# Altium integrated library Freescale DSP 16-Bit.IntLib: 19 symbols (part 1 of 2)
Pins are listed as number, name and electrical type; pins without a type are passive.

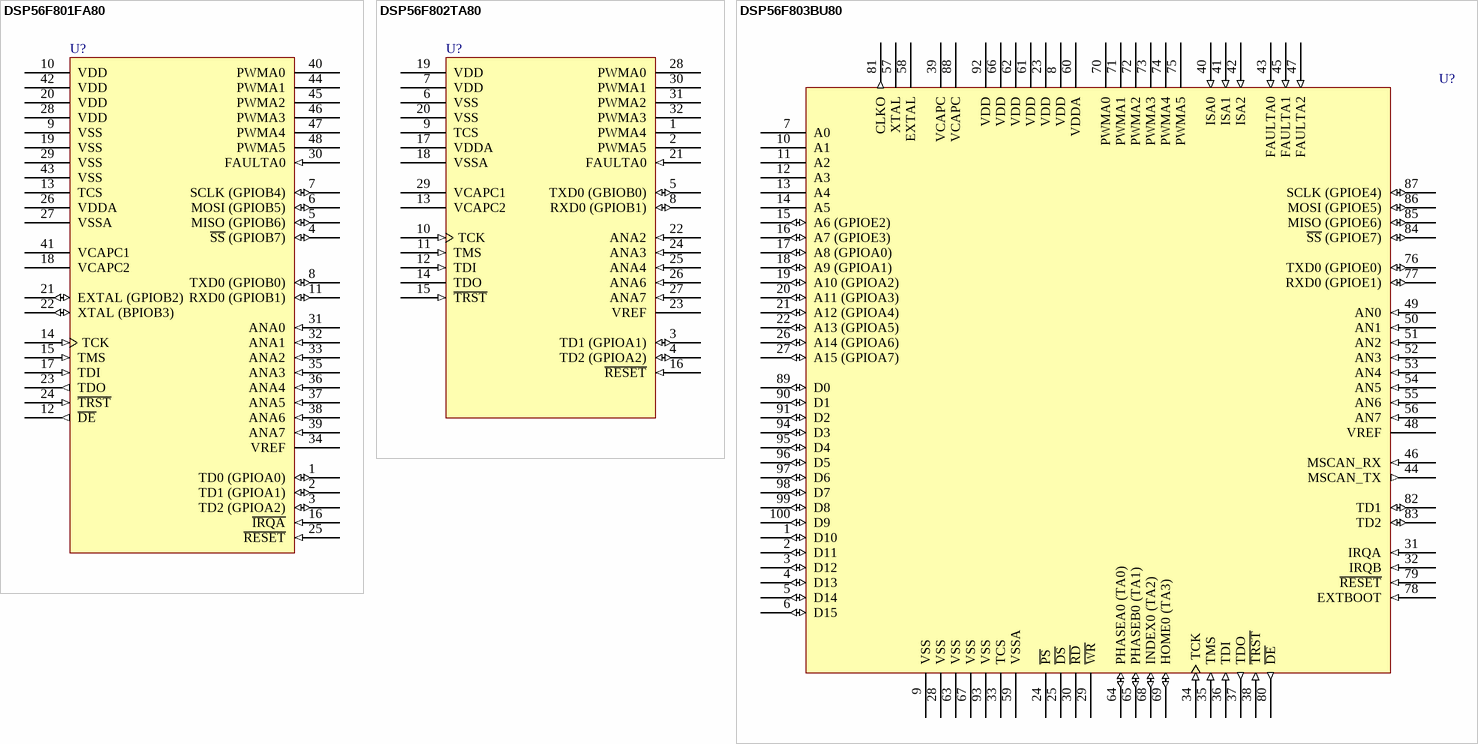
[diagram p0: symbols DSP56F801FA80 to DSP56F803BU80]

## DSP56F801FA80
designator U?
DSP56800 General Purpose 16-Bit Fixed Point DSP
footprint 932-03_N (Thin QFP, 48-Leads, Body 7x7mm, Pitch 0.5mm, IPC Medium Density)
footprint 932-03_L (Thin QFP, 48-Leads, Body 7x7mm, Pitch 0.5mm, IPC High Density)
footprint 932-03_M (Thin QFP, 48-Leads, Body 7x7mm, Pitch 0.5mm, IPC Low Density)
3D model DSP56F801-932-03 (48-Pin Thin Quad Flat Pack 0.5 mm Pitch)
pins: 1 TD0 (GPIOA0) (io), 2 TD1 (GPIOA1) (io), 3 TD2 (GPIOA2) (io), 4 ~{SS} (GPIOB7) (io), 5 MISO (GPIOB6) (io), 6 MOSI (GPIOB5) (io), 7 SCLK (GPIOB4) (io), 8 TXD0 (GPIOB0) (io), 9 VSS (power), 10 VDD (power), 11 RXD0 (GPIOB1) (io), 12 ~{DE} (out), 13 TCS, 14 TCK (in), 15 TMS (in), 16 ~{IRQA} (in), 17 TDI (in), 18 VCAPC2 (power), 19 VSS (power), 20 VDD (power), 21 EXTAL (GPIOB2) (io), 22 XTAL (BPIOB3) (io), 23 TDO (out), 24 ~{TRST} (in), 25 ~{RESET} (in), 26 VDDA (power), 27 VSSA (power), 28 VDD (power), 29 VSS (power), 30 FAULTA0 (in), 31 ANA0 (in), 32 ANA1 (in), 33 ANA2 (in), 34 VREF, 35 ANA3 (in), 36 ANA4 (in), 37 ANA5 (in), 38 ANA6 (in), 39 ANA7 (in), 40 PWMA0 (hiz), 41 VCAPC1 (power), 42 VDD (power), 43 VSS (power), 44 PWMA1 (hiz), 45 PWMA2 (hiz), 46 PWMA3 (hiz), 47 PWMA4 (hiz), 48 PWMA5 (hiz)

## DSP56F802TA80
designator U?
DSP56800 General Purpose 16-Bit Fixed Point DSP
footprint 873A_N (Thin QFP, 32-Leads, Body 7x7mm, Pitch 0.8mm, IPC Medium Density)
footprint 873A_L (Thin QFP, 32-Leads, Body 7x7mm, Pitch 0.8mm, IPC High Density)
footprint 873A_M (Thin QFP, 32-Leads, Body 7x7mm, Pitch 0.8mm, IPC Low Density)
3D model DSP56F802-873A (32-Pin Thin Quad Flat Pack 0.8 mm Pitch)
pins: 1 PWMA4 (hiz), 2 PWMA5 (hiz), 3 TD1 (GPIOA1) (io), 4 TD2 (GPIOA2) (io), 5 TXD0 (GBIOB0) (io), 6 VSS (power), 7 VDD (power), 8 RXD0 (GPIOB1) (io), 9 TCS, 10 TCK (in), 11 TMS (in), 12 TDI (in), 13 VCAPC2 (power), 14 TDO (hiz), 15 ~{TRST} (in), 16 ~{RESET} (in), 17 VDDA (power), 18 VSSA (power), 19 VDD (power), 20 VSS (power), 21 FAULTA0 (in), 22 ANA2 (in), 23 VREF, 24 ANA3 (in), 25 ANA4 (in), 26 ANA6 (in), 27 ANA7 (in), 28 PWMA0 (hiz), 29 VCAPC1 (power), 30 PWMA1 (hiz), 31 PWMA2 (hiz), 32 PWMA3 (hiz)

## DSP56F803BU80
designator U?
DSP56800 General Purpose 16-Bit Fixed Point DSP
footprint 842F-01_N (Thin QFP, 100-Leads, Body 14x14mm, Pitch 0.5mm, IPC Medium Density)
footprint 842F-01_L (Thin QFP, 100-Leads, Body 14x14mm, Pitch 0.5mm, IPC High Density)
footprint 842F-01_M (Thin QFP, 100-Leads, Body 14x14mm, Pitch 0.5mm, IPC Low Density)
3D model DSP56F803-842F-01 (100-Pin Thin Quad Flat Pack 0.5 mm Pitch)
pins: 1 D10 (io), 2 D11 (io), 3 D12 (io), 4 D13 (io), 5 D14 (io), 6 D15 (io), 7 A0 (hiz), 8 VDD (power), 9 VSS (power), 10 A1 (hiz), 11 A2 (hiz), 12 A3 (hiz), 13 A4 (hiz), 14 A5 (hiz), 15 A6 (GPIOE2) (io), 16 A7 (GPIOE3) (io), 17 A8 (GPIOA0) (io), 18 A9 (GPIOA1) (io), 19 A10 (GPIOA2) (io), 20 A11 (GPIOA3) (io), 21 A12 (GPIOA4) (io), 22 A13 (GPIOA5) (io), 23 VDD (power), 24 ~{PS} (hiz), 25 ~{DS} (hiz), 26 A14 (GPIOA6) (io), 27 A15 (GPIOA7) (io), 28 VSS (power), 29 ~{WR} (hiz), 30 ~{RD} (hiz), 31 IRQA (in), 32 IRQB (in), 33 TCS, 34 TCK (in), 35 TMS (in), 36 TDI (in), 37 TDO (out), 38 ~{TRST} (in), 39 VCAPC (power), 40 ISA0 (in), 41 ISA1 (in), 42 ISA2 (in), 43 FAULTA0 (in), 44 MSCAN_TX (out), 45 FAULTA1 (in), 46 MSCAN_RX (in), 47 FAULTA2 (in), 48 VREF, 49 AN0 (in), 50 AN1 (in), 51 AN2 (in), 52 AN3 (in), 53 AN4 (in), 54 AN5 (in), 55 AN6 (in), 56 AN7 (in), 57 XTAL, 58 EXTAL, 59 VSSA (power), 60 VDDA (power), 61 VDD (power), 62 VDD (power), 63 VSS (power), 64 PHASEA0 (TA0) (io), 65 PHASEB0 (TA1) (io), 66 VDD (power), 67 VSS (power), 68 INDEX0 (TA2) (io), 69 HOME0 (TA3) (io), 70 PWMA0 (hiz), 71 PWMA1 (hiz), 72 PWMA2 (hiz), 73 PWMA3 (hiz), 74 PWMA4 (hiz), 75 PWMA5 (hiz), 76 TXD0 (GPIOE0) (io), 77 RXD0 (GPIOE1) (io), 78 EXTBOOT (in), 79 ~{RESET} (in), 80 ~{DE} (out), 81 CLKO (out), 82 TD1 (io), 83 TD2 (io), 84 ~{SS} (GPIOE7) (io), 85 MISO (GPIOE6) (io), 86 MOSI (GPIOE5) (io), 87 SCLK (GPIOE4) (io), 88 VCAPC (power), 89 D0 (io), 90 D1 (io), 91 D2 (io), 92 VDD (power), 93 VSS (power), 94 D3 (io), 95 D4 (io), 96 D5 (io), 97 D6 (io), 98 D7 (io), 99 D8 (io), 100 D9 (io)

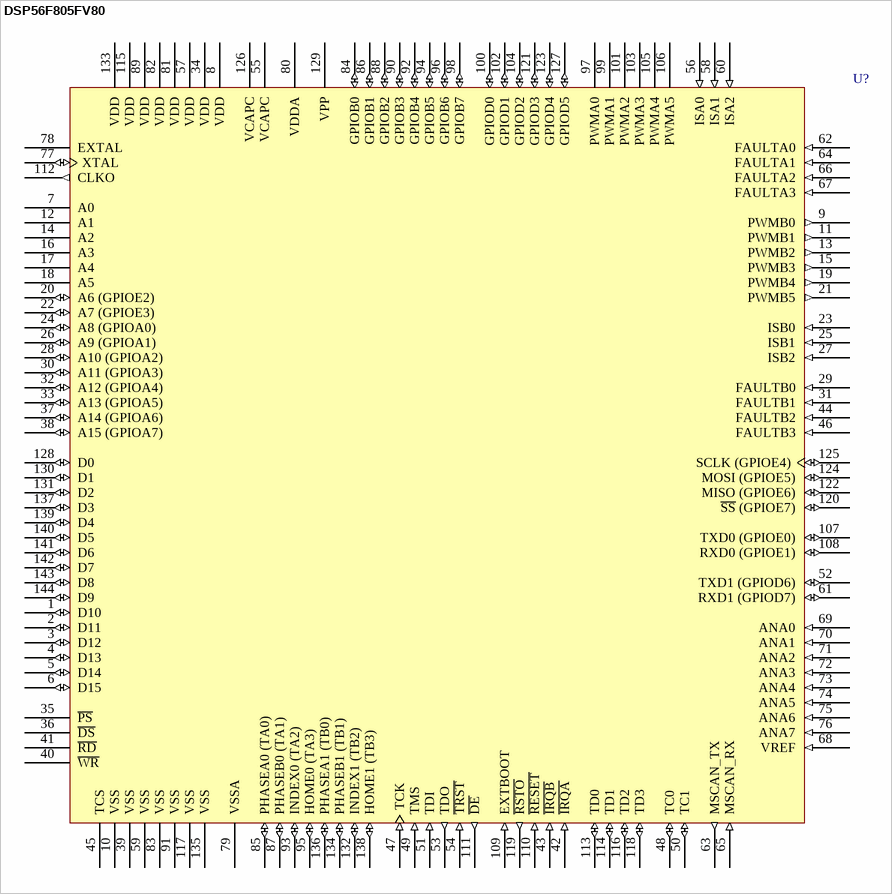
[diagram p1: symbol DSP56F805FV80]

## DSP56F805FV80
designator U?
DSP56800 General Purpose 16-Bit Fixed Point DSP
footprint 918-03_N (Thin QFP, 144-Leads, Body 20x20mm, Pitch 0.5mm, IPC Medium Density)
footprint 918-03_L (Thin QFP, 144-Leads, Body 20x20mm, Pitch 0.5mm, IPC High Density)
footprint 918-03_M (Thin QFP, 144-Leads, Body 20x20mm, Pitch 0.5mm, IPC Low Density)
3D model DSP56F805-918-03 (144-Pin Low Profile Quad Flat Pack 0.5 mm Pitch (918-03))
pins: 1 D10 (io), 2 D11 (io), 3 D12 (io), 4 D13 (io), 5 D14 (io), 6 D15 (io), 7 A0 (hiz), 8 VDD (power), 9 PWMB0 (out), 10 VSS (power), 11 PWMB1 (out), 12 A1 (hiz), 13 PWMB2 (out), 14 A2 (hiz), 15 PWMB3 (out), 16 A3 (hiz), 17 A4 (hiz), 18 A5 (hiz), 19 PWMB4 (out), 20 A6 (GPIOE2) (io), 21 PWMB5 (out), 22 A7 (GPIOE3) (io), 23 ISB0 (in), 24 A8 (GPIOA0) (io), 25 ISB1 (in), 26 A9 (GPIOA1) (io), 27 ISB2 (in), 28 A10 (GPIOA2) (io), 29 FAULTB0 (in), 30 A11 (GPIOA3) (io), 31 FAULTB1 (in), 32 A12 (GPIOA4) (io), 33 A13 (GPIOA5) (io), 34 VDD (power), 35 ~{PS} (hiz), 36 ~{DS} (hiz), 37 A14 (GPIOA6) (io), 38 A15 (GPIOA7) (io), 39 VSS (power), 40 ~{WR} (hiz), 41 ~{RD} (hiz), 42 ~{IRQA} (in), 43 ~{IRQB} (in), 44 FAULTB2 (in), 45 TCS, 46 FAULTB3 (in), 47 TCK (in), 48 TC0 (io), 49 TMS (in), 50 TC1 (io), 51 TDI (in), 52 TXD1 (GPIOD6) (io), 53 TDO (out), 54 ~{TRST} (in), 55 VCAPC (power), 56 ISA0 (in), 57 VDD (power), 58 ISA1 (in), 59 VSS (power), 60 ISA2 (in), 61 RXD1 (GPIOD7) (io), 62 FAULTA0 (in), 63 MSCAN_TX (out), 64 FAULTA1 (in), 65 MSCAN_RX (in), 66 FAULTA2 (in), 67 FAULTA3 (in), 68 VREF (in), 69 ANA0 (in), 70 ANA1 (in), 71 ANA2 (in), 72 ANA3 (in), 73 ANA4 (in), 74 ANA5 (in), 75 ANA6 (in), 76 ANA7 (in), 77 XTAL (io), 78 EXTAL, 79 VSSA (power), 80 VDDA (power), 81 VDD (power), 82 VDD (power), 83 VSS (power), 84 GPIOB0 (io), 85 PHASEA0 (TA0) (io), 86 GPIOB1 (io), 87 PHASEB0 (TA1) (io), 88 GPIOB2 (io), 89 VDD (power), 90 GPIOB3 (io), 91 VSS (power), 92 GPIOB4 (io), 93 INDEX0 (TA2) (io), 94 GPIOB5 (io), 95 HOME0 (TA3) (io), 96 GPIOB6 (io), 97 PWMA0 (hiz), 98 GPIOB7 (io), 99 PWMA1 (hiz), 100 GPIOD0 (io), 101 PWMA2 (hiz), 102 GPIOD1 (io), 103 PWMA3 (hiz), 104 GPIOD2 (io), 105 PWMA4 (hiz), 106 PWMA5 (hiz), 107 TXD0 (GPIOE0) (io), 108 RXD0 (GPIOE1) (io), 109 EXTBOOT (in), 110 ~{RESET} (in), 111 ~{DE} (out), 112 CLKO (out), 113 TD0 (io), 114 TD1 (io), 115 VDD (power), 116 TD2 (io), 117 VSS (power), 118 TD3 (io), 119 ~{RSTO} (out), 120 ~{SS} (GPIOE7) (io), 121 GPIOD3 (io), 122 MISO (GPIOE6) (io), 123 GPIOD4 (io), 124 MOSI (GPIOE5) (io), 125 SCLK (GPIOE4) (io), 126 VCAPC (power), 127 GPIOD5 (io), 128 D0 (io), 129 VPP (power), 130 D1 (io), 131 D2 (io), 132 INDEX1 (TB2) (io), 133 VDD (power), 134 PHASEB1 (TB1) (io), 135 VSS (power), 136 PHASEA1 (TB0) (io), 137 D3 (io), 138 HOME1 (TB3) (io), 139 D4 (io), 140 D5 (io), 141 D6 (io), 142 D7 (io), 143 D8 (io), 144 D9 (io)

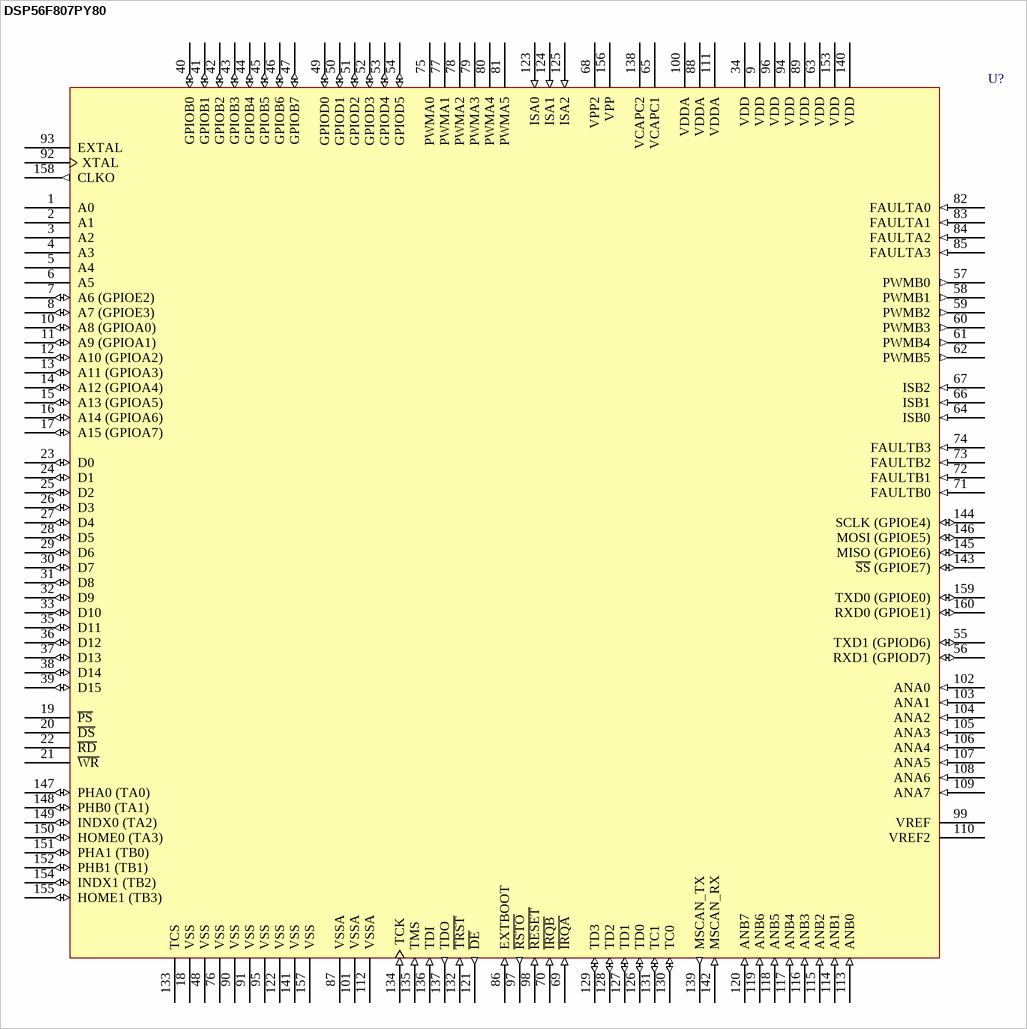
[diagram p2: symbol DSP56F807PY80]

## DSP56F807PY80
designator U?
DSP56800 General Purpose 16-Bit Fixed Point DSP
footprint 1259-01_N (Thin QFP, 160-Leads, Body 24x24mm, Pitch 0.5mm, IPC Medium Density)
footprint 1259-01_L (Thin QFP, 160-Leads, Body 24x24mm, Pitch 0.5mm, IPC High Density)
footprint 1259-01_M (Thin QFP, 160-Leads, Body 24x24mm, Pitch 0.5mm, IPC Low Density)
3D model DSP56F807-1259-01 (160-Pin Thin Quad Flat Pack 0.5 mm Pitch)
pins: 1 A0 (hiz), 2 A1 (hiz), 3 A2 (hiz), 4 A3 (hiz), 5 A4 (hiz), 6 A5 (hiz), 7 A6 (GPIOE2) (io), 8 A7 (GPIOE3) (io), 9 VDD (power), 10 A8 (GPIOA0) (io), 11 A9 (GPIOA1) (io), 12 A10 (GPIOA2) (io), 13 A11 (GPIOA3) (io), 14 A12 (GPIOA4) (io), 15 A13 (GPIOA5) (io), 16 A14 (GPIOA6) (io), 17 A15 (GPIOA7) (io), 18 VSS (power), 19 ~{PS} (hiz), 20 ~{DS} (hiz), 21 ~{WR} (hiz), 22 ~{RD} (hiz), 23 D0 (io), 24 D1 (io), 25 D2 (io), 26 D3 (io), 27 D4 (io), 28 D5 (io), 29 D6 (io), 30 D7 (io), 31 D8 (io), 32 D9 (io), 33 D10 (io), 34 VDD (power), 35 D11 (io), 36 D12 (io), 37 D13 (io), 38 D14 (io), 39 D15 (io), 40 GPIOB0 (io), 41 GPIOB1 (io), 42 GPIOB2 (io), 43 GPIOB3 (io), 44 GPIOB4 (io), 45 GPIOB5 (io), 46 GPIOB6 (io), 47 GPIOB7 (io), 48 VSS (power), 49 GPIOD0 (io), 50 GPIOD1 (io), 51 GPIOD2 (io), 52 GPIOD3 (io), 53 GPIOD4 (io), 54 GPIOD5 (io), 55 TXD1 (GPIOD6) (io), 56 RXD1 (GPIOD7) (io), 57 PWMB0 (out), 58 PWMB1 (out), 59 PWMB2 (out), 60 PWMB3 (out), 61 PWMB4 (out), 62 PWMB5 (out), 63 VDD (power), 64 ISB0 (in), 65 VCAPC1 (power), 66 ISB1 (in), 67 ISB2 (in), 68 VPP2, 69 ~{IRQA} (in), 70 ~{IRQB} (in), 71 FAULTB0 (in), 72 FAULTB1 (in), 73 FAULTB2 (in), 74 FAULTB3 (in), 75 PWMA0 (hiz), 76 VSS (power), 77 PWMA1 (hiz), 78 PWMA2 (hiz), 79 PWMA3 (hiz), 80 PWMA4 (hiz), 81 PWMA5 (hiz), 82 FAULTA0 (in), 83 FAULTA1 (in), 84 FAULTA2 (in), 85 FAULTA3 (in), 86 EXTBOOT (in), 87 VSSA (power), 88 VDDA (power), 89 VDD (power), 90 VSS (power), 91 VSS (power), 92 XTAL, 93 EXTAL, 94 VDD (power), 95 VSS (power), 96 VDD (power), 97 ~{RSTO} (out), 98 ~{RESET} (in), 99 VREF, 100 VDDA (power), 101 VSSA (power), 102 ANA0 (in), 103 ANA1 (in), 104 ANA2 (in), 105 ANA3 (in), 106 ANA4 (in), 107 ANA5 (in), 108 ANA6 (in), 109 ANA7 (in), 110 VREF2, 111 VDDA (power), 112 VSSA (power), 113 ANB0 (in), 114 ANB1 (in), 115 ANB2 (in), 116 ANB3 (in), 117 ANB4 (in), 118 ANB5 (in), 119 ANB6 (in), 120 ANB7 (in), 121 ~{DE} (out), 122 VSS (power), 123 ISA0 (in), 124 ISA1 (in), 125 ISA2 (in), 126 TD0 (io), 127 TD1 (io), 128 TD2 (io), 129 TD3 (io), 130 TC0 (io), 131 TC1 (io), 132 ~{TRST} (in), 133 TCS, 134 TCK (in), 135 TMS (in), 136 TDI (in), 137 TDO (out), 138 VCAPC2 (power), 139 MSCAN_TX (out), 140 VDD (power), 141 VSS (power), 142 MSCAN_RX (in), 143 ~{SS} (GPIOE7) (io), 144 SCLK (GPIOE4) (io), 145 MISO (GPIOE6) (io), 146 MOSI (GPIOE5) (io), 147 PHA0 (TA0) (io), 148 PHB0 (TA1) (io), 149 INDX0 (TA2) (io), 150 HOME0 (TA3) (io), 151 PHA1 (TB0) (io), 152 PHB1 (TB1) (io), 153 VDD (power), 154 INDX1 (TB2) (io), 155 HOME1 (TB3) (io), 156 VPP, 157 VSS (power), 158 CLKO (out), 159 TXD0 (GPIOE0) (io), 160 RXD0 (GPIOE1) (io)

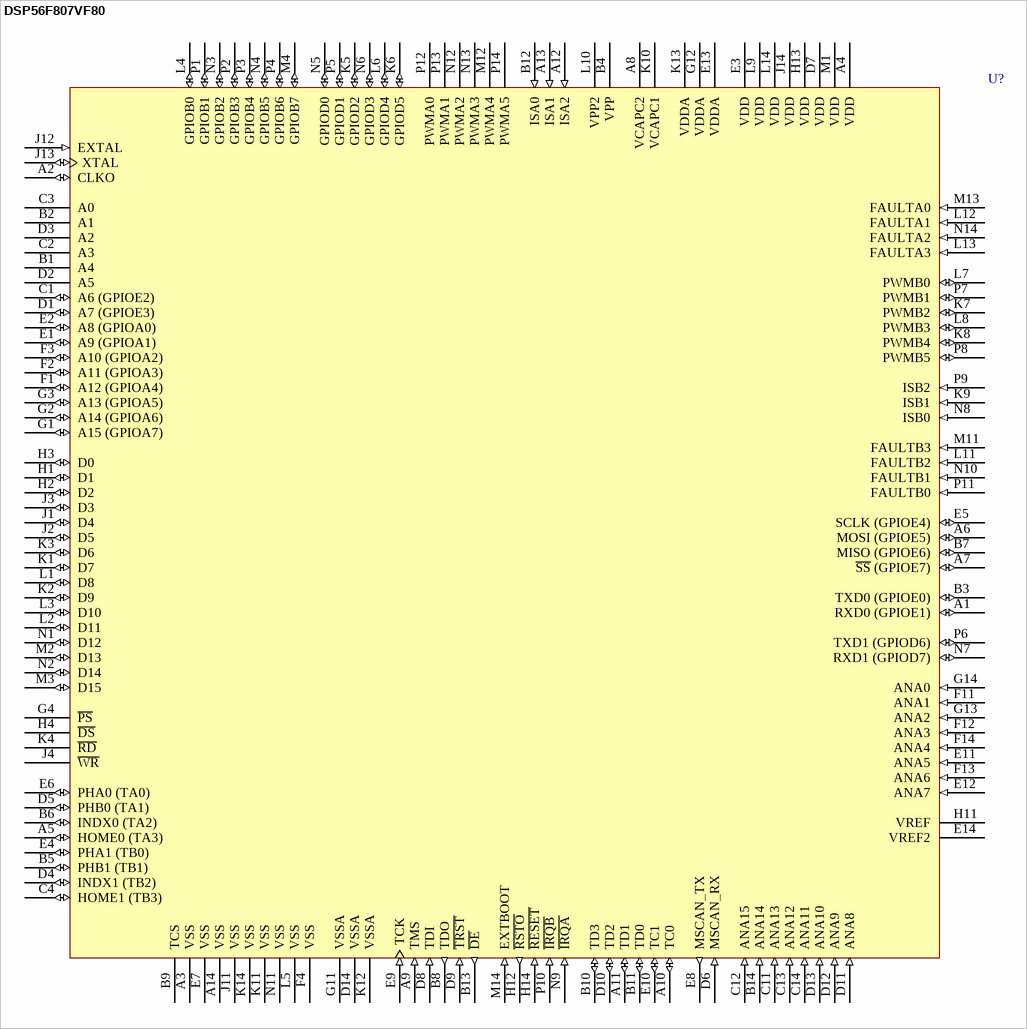
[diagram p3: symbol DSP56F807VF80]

## DSP56F807VF80
designator U?
DSP56800 General Purpose 16-Bit Fixed Point DSP
footprint 1268-01 (BGA, 160-Leads, Body 15x15mm, Pitch 1mm)
3D model DSP56F807-1268-01 (160-Ball MAP-Ball Grid Array 1 mm Pitch)
pins: A1 RXD0 (GPIOE1) (io), A2 CLKO (io), A3 VSS (power), A4 VDD (power), A5 HOME0 (TA3) (io), A6 MOSI (GPIOE5) (io), A7 ~{SS} (GPIOE7) (io), A8 VCAPC2, A9 TMS (in), A10 TC0 (io), A11 TD1 (io), A12 ISA2 (in), A13 ISA1 (in), A14 VSS (power), B1 A4 (hiz), B2 A1 (hiz), B3 TXD0 (GPIOE0) (io), B4 VPP, B5 PHB1 (TB1) (io), B6 INDX0 (TA2) (io), B7 MISO (GPIOE6) (io), B8 TDO (out), B9 TCS, B10 TD3 (io), B11 TD0 (io), B12 ISA0 (in), B13 ~{DE} (out), B14 ANA14 (in), C1 A6 (GPIOE2) (io), C2 A3 (hiz), C3 A0 (hiz), C4 HOME1 (TB3) (io), C11 ANA13 (in), C12 ANA15 (in), C13 ANA12 (in), C14 ANA11 (in), D1 A7 (GPIOE3) (io), D2 A5 (hiz), D3 A2 (hiz), D4 INDX1 (TB2) (io), D5 PHB0 (TA1) (io), D6 MSCAN_RX (in), D7 VDD (power), D8 TDI (in), D9 ~{TRST} (in), D10 TD2 (io), D11 ANA8 (in), D12 ANA9 (in), D13 ANA10 (in), D14 VSSA (power), E1 A9 (GPIOA1) (io), E2 A8 (GPIOA0) (io), E3 VDD (power), E4 PHA1 (TB0) (io), E5 SCLK (GPIOE4) (io), E6 PHA0 (TA0) (io), E7 VSS (power), E8 MSCAN_TX (out), E9 TCK (in), E10 TC1 (io), E11 ANA5 (in), E12 ANA7 (in), E13 VDDA (power), E14 VREF2, F1 A12 (GPIOA4) (io), F2 A11 (GPIOA3) (io), F3 A10 (GPIOA2) (io), F4 VSS (power), F11 ANA1 (in), F12 ANA3 (in), F13 ANA6 (in), F14 ANA4 (in), G1 A15 (GPIOA7) (io), G2 A14 (GPIOA6) (io), G3 A13 (GPIOA5) (io), G4 ~{PS} (hiz), G11 VSSA (power), G12 VDDA (power), G13 ANA2 (in), G14 ANA0 (in), H1 D1 (io), H2 D2 (io), H3 D0 (io), H4 ~{DS} (hiz), H11 VREF, H12 ~{RSTO} (out), H13 VDD (power), H14 ~{RESET} (in), J1 D4 (io), J2 D5 (io), J3 D3 (io), J4 ~{WR} (hiz), J11 VSS (power), J12 EXTAL (in), J13 XTAL (io), J14 VDD (power), K1 D7 (io), K2 D9 (io), K3 D6 (io), K4 ~{RD} (hiz), K5 GPIOD2 (io), K6 GPIOD5 (io), K7 PWMB2 (io), K8 PWMB4 (io), K9 ISB1 (in), K10 VCAPC1, K11 VSS (power), K12 VSSA (power), K13 VDDA (power), K14 VSS (power), L1 D8 (io), L2 D11 (io), L3 D10 (io), L4 GPIOB0 (io), L5 VSS (power), L6 GPIOD4 (io), L7 PWMB0 (io), L8 PWMB3 (io), L9 VDD (power), L10 VPP2, L11 FAULTB2 (in), L12 FAULTA1 (in), L13 FAULTA3 (in), L14 VDD (power), M1 VDD (power), M2 D13 (io), M3 D15 (io), M4 GPIOB7 (io), M11 FAULTB3 (in), M12 PWMA4 (hiz), M13 FAULTA0 (in), M14 EXTBOOT (in), N1 D12 (io), N2 D14 (io), N3 GPIOB2 (io), N4 GPIOB5 (io), N5 GPIOD0 (io), N6 GPIOD3 (io), N7 RXD1 (GPIOD7) (io), N8 ISB0 (in), N9 ~{IRQA} (in), N10 FAULTB1 (in), N11 VSS (power), N12 PWMA2 (hiz), N13 PWMA3 (hiz), N14 FAULTA2 (in), P1 GPIOB1 (io), P2 GPIOB3 (io), P3 GPIOB4 (io), P4 GPIOB6 (io), P5 GPIOD1 (io), P6 TXD1 (GPIOD6) (io), P7 PWMB1 (io), P8 PWMB5 (io), P9 ISB2 (in), P10 ~{IRQB} (in), P11 FAULTB0 (in), P12 PWMA0 (hiz), P13 PWMA1 (hiz), P14 PWMA5 (hiz)

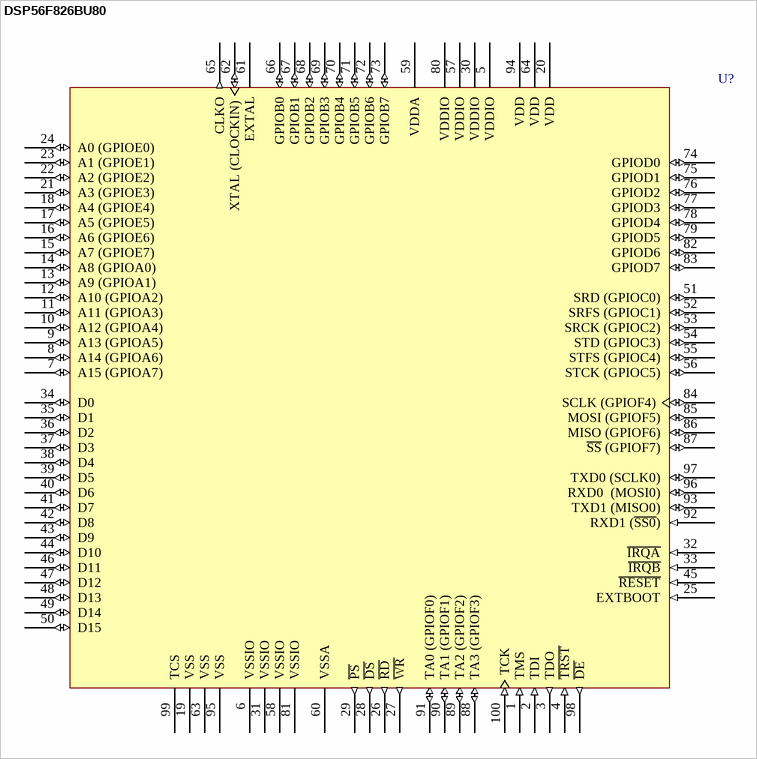
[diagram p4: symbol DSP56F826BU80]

## DSP56F826BU80
designator U?
DSP56800 General Purpose 16-Bit Fixed Point DSP
footprint 842F-01_N (Thin QFP, 100-Leads, Body 14x14mm, Pitch 0.5mm, IPC Medium Density)
footprint 842F-01_L (Thin QFP, 100-Leads, Body 14x14mm, Pitch 0.5mm, IPC High Density)
footprint 842F-01_M (Thin QFP, 100-Leads, Body 14x14mm, Pitch 0.5mm, IPC Low Density)
3D model DSP56F826-842F-01 (100-Pin Thin Quad Flat Pack 0.5 mm Pitch)
pins: 1 TMS (in), 2 TDI (in), 3 TDO (out), 4 ~{TRST} (in), 5 VDDIO (power), 6 VSSIO (power), 7 A15 (GPIOA7) (io), 8 A14 (GPIOA6) (io), 9 A13 (GPIOA5) (io), 10 A12 (GPIOA4) (io), 11 A11 (GPIOA3) (io), 12 A10 (GPIOA2) (io), 13 A9 (GPIOA1) (io), 14 A8 (GPIOA0) (io), 15 A7 (GPIOE7) (io), 16 A6 (GPIOE6) (io), 17 A5 (GPIOE5) (io), 18 A4 (GPIOE4) (io), 19 VSS (power), 20 VDD (power), 21 A3 (GPIOE3) (io), 22 A2 (GPIOE2) (io), 23 A1 (GPIOE1) (io), 24 A0 (GPIOE0) (io), 25 EXTBOOT (in), 26 ~{RD} (out), 27 ~{WR} (out), 28 ~{DS} (out), 29 ~{PS} (out), 30 VDDIO (power), 31 VSSIO (power), 32 ~{IRQA} (in), 33 ~{IRQB} (in), 34 D0 (io), 35 D1 (io), 36 D2 (io), 37 D3 (io), 38 D4 (io), 39 D5 (io), 40 D6 (io), 41 D7 (io), 42 D8 (io), 43 D9 (io), 44 D10 (io), 45 ~{RESET} (in), 46 D11 (io), 47 D12 (io), 48 D13 (io), 49 D14 (io), 50 D15 (io), 51 SRD (GPIOC0) (io), 52 SRFS (GPIOC1) (io), 53 SRCK (GPIOC2) (io), 54 STD (GPIOC3) (io), 55 STFS (GPIOC4) (io), 56 STCK (GPIOC5) (io), 57 VDDIO (power), 58 VSSIO (power), 59 VDDA (power), 60 VSSA (power), 61 EXTAL, 62 XTAL (CLOCKIN) (io), 63 VSS (power), 64 VDD (power), 65 CLKO (out), 66 GPIOB0 (io), 67 GPIOB1 (io), 68 GPIOB2 (io), 69 GPIOB3 (io), 70 GPIOB4 (io), 71 GPIOB5 (io), 72 GPIOB6 (io), 73 GPIOB7 (io), 74 GPIOD0 (io), 75 GPIOD1 (io), 76 GPIOD2 (io), 77 GPIOD3 (io), 78 GPIOD4 (io), 79 GPIOD5 (io), 80 VDDIO (power), 81 VSSIO (power), 82 GPIOD6 (io), 83 GPIOD7 (io), 84 SCLK (GPIOF4) (io), 85 MOSI (GPIOF5) (io), 86 MISO (GPIOF6) (io), 87 ~{SS} (GPIOF7) (io), 88 TA3 (GPIOF3) (io), 89 TA2 (GPIOF2) (io), 90 TA1 (GPIOF1) (io), 91 TA0 (GPIOF0) (io), 92 RXD1 (~{SS0}) (in), 93 TXD1 (MISO0) (io), 94 VDD (power), 95 VSS (power), 96 RXD0  (MOSI0) (io), 97 TXD0 (SCLK0) (io), 98 ~{DE} (out), 99 TCS, 100 TCK (in)

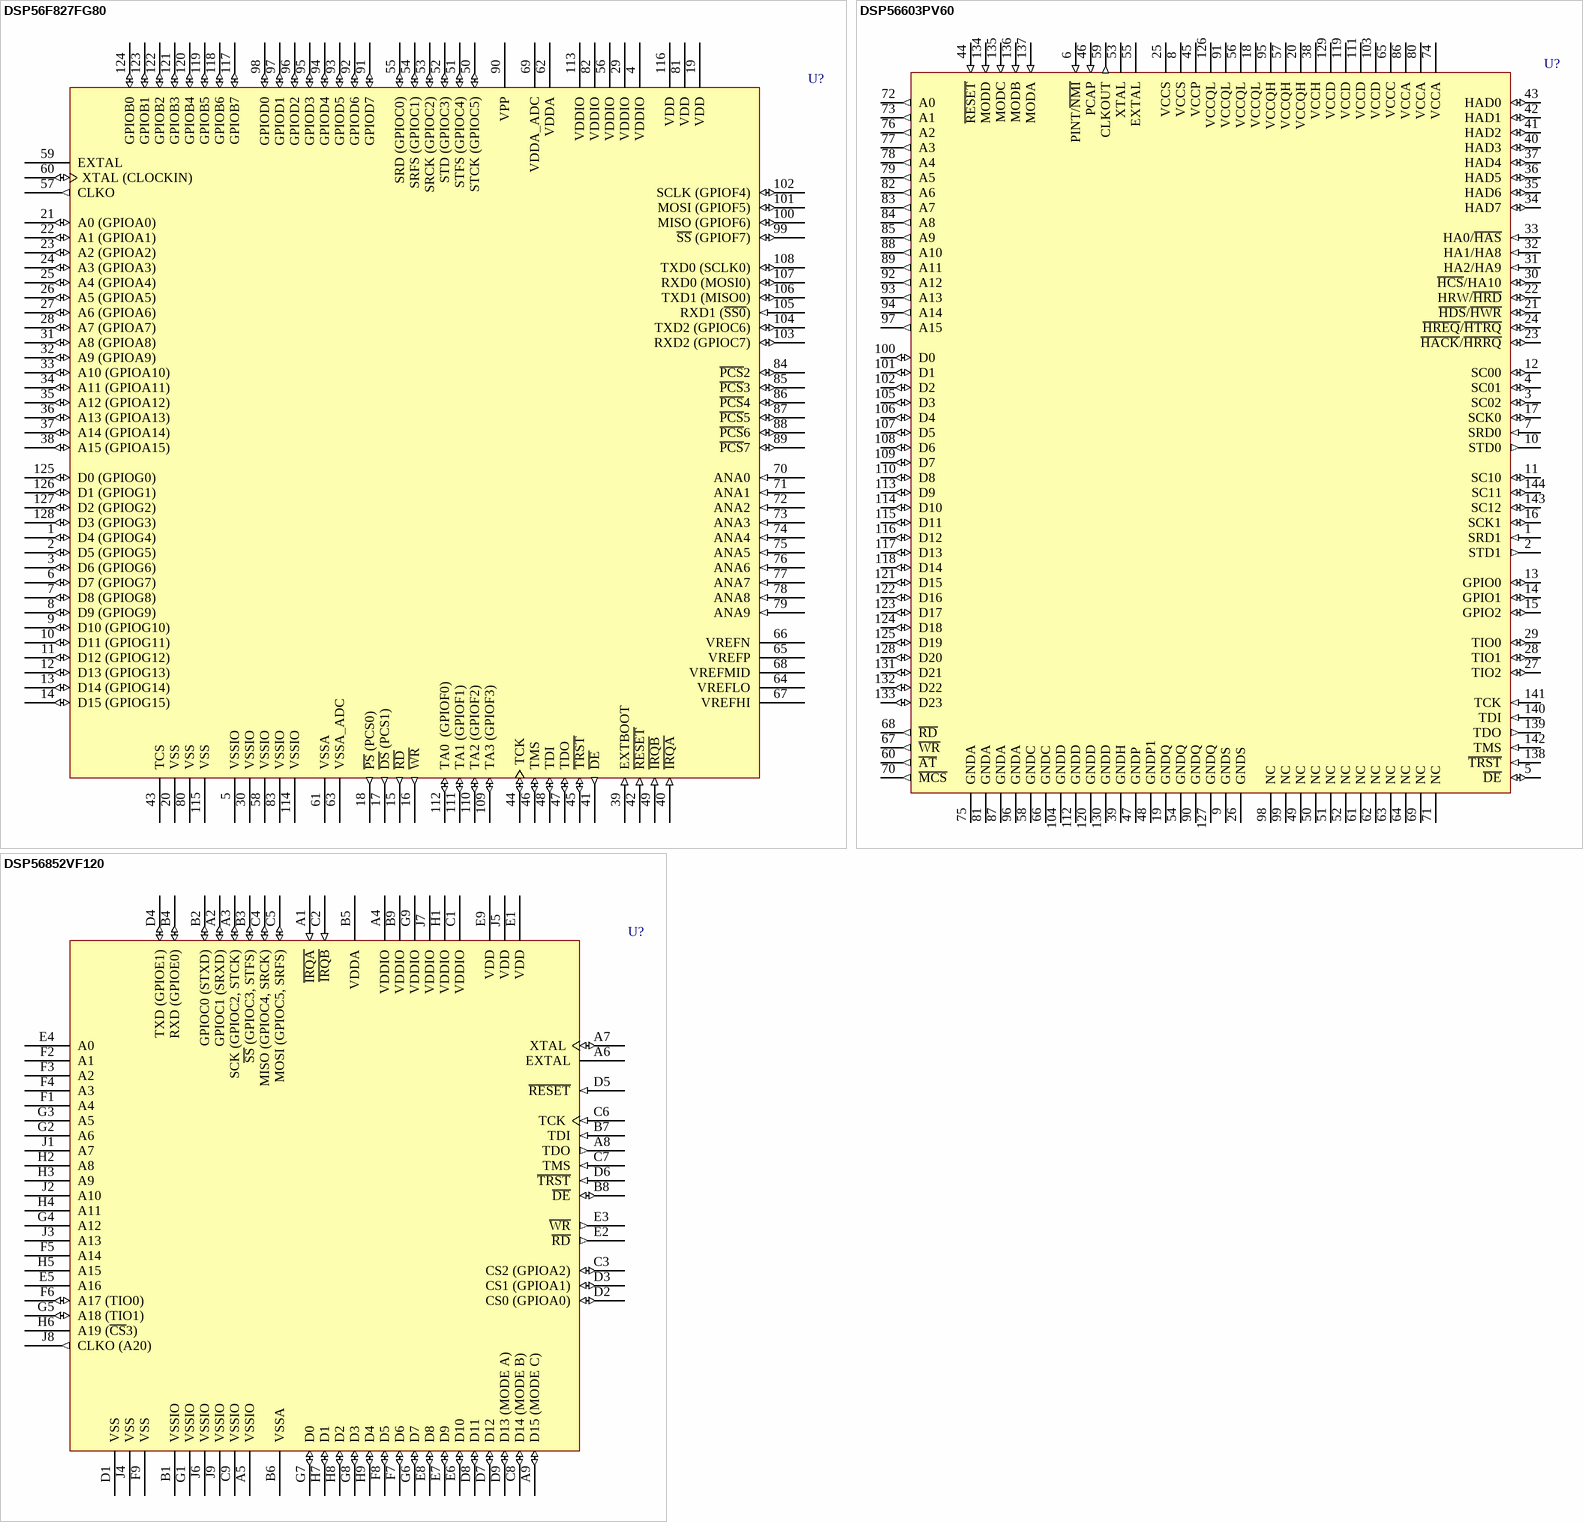
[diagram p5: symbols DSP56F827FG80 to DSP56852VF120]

## DSP56F827FG80
designator U?
DSP56800 General Purpose 16-Bit Fixed Point DSP
footprint 1129-01_N (Thin QFP, 128-Leads, Body 20x14 mm, Pitch 0.5mm, IPC Medium Density)
footprint 1129-01_L (Thin QFP, 128-Leads, Body 20x14 mm, Pitch 0.5mm, IPC High Density)
footprint 1129-01_M (Thin QFP, 128-Leads, Body 20x14 mm, Pitch 0.5mm, IPC Low Density)
3D model DSP56F827-1129-01 (128-Pin Thin Quad Flat Pack Rectangular 0.5 mm Pitch)
pins: 1 D4 (GPIOG4) (io), 2 D5 (GPIOG5) (io), 3 D6 (GPIOG6) (io), 4 VDDIO (power), 5 VSSIO (power), 6 D7 (GPIOG7) (io), 7 D8 (GPIOG8) (io), 8 D9 (GPIOG9) (io), 9 D10 (GPIOG10) (io), 10 D11 (GPIOG11) (io), 11 D12 (GPIOG12) (io), 12 D13 (GPIOG13) (io), 13 D14 (GPIOG14) (io), 14 D15 (GPIOG15) (io), 15 ~{RD} (out), 16 ~{WR} (out), 17 ~{DS} (PCS1) (out), 18 ~{PS} (PCS0) (out), 19 VDD (power), 20 VSS (power), 21 A0 (GPIOA0) (io), 22 A1 (GPIOA1) (io), 23 A2 (GPIOA2) (io), 24 A3 (GPIOA3) (io), 25 A4 (GPIOA4) (io), 26 A5 (GPIOA5) (io), 27 A6 (GPIOA6) (io), 28 A7 (GPIOA7) (io), 29 VDDIO (power), 30 VSSIO (power), 31 A8 (GPIOA8) (io), 32 A9 (GPIOA9) (io), 33 A10 (GPIOA10) (io), 34 A11 (GPIOA11) (io), 35 A12 (GPIOA12) (io), 36 A13 (GPIOA13) (io), 37 A14 (GPIOA14) (io), 38 A15 (GPIOA15) (io), 39 EXTBOOT (in), 40 ~{IRQA} (in), 41 ~{DE} (out), 42 ~{RESET} (in), 43 TCS, 44 TCK (io), 45 ~{TRST} (io), 46 TMS (io), 47 TDO (io), 48 TDI (io), 49 ~{IRQB} (in), 50 STCK (GPIOC5) (io), 51 STFS (GPIOC4) (io), 52 STD (GPIOC3) (io), 53 SRCK (GPIOC2) (io), 54 SRFS (GPIOC1) (io), 55 SRD (GPIOC0) (io), 56 VDDIO (power), 57 CLKO (out), 58 VSSIO (power), 59 EXTAL, 60 XTAL (CLOCKIN) (io), 61 VSSA (power), 62 VDDA (power), 63 VSSA_ADC (power), 64 VREFLO, 65 VREFP, 66 VREFN, 67 VREFHI, 68 VREFMID, 69 VDDA_ADC (power), 70 ANA0 (in), 71 ANA1 (in), 72 ANA2 (in), 73 ANA3 (in), 74 ANA4 (in), 75 ANA5 (in), 76 ANA6 (in), 77 ANA7 (in), 78 ANA8 (in), 79 ANA9 (in), 80 VSS (power), 81 VDD (power), 82 VDDIO (power), 83 VSSIO (power), 84 ~{PCS}2 (io), 85 ~{PCS}3 (io), 86 ~{PCS}4 (io), 87 ~{PCS}5 (io), 88 ~{PCS}6 (io), 89 ~{PCS}7 (io), 90 VPP, 91 GPIOD7 (io), 92 GPIOD6 (io), 93 GPIOD5 (io), 94 GPIOD4 (io), 95 GPIOD3 (io), 96 GPIOD2 (io), 97 GPIOD1 (io), 98 GPIOD0 (io), 99 ~{SS} (GPIOF7) (io), 100 MISO (GPIOF6) (io), 101 MOSI (GPIOF5) (io), 102 SCLK (GPIOF4) (io), 103 RXD2 (GPIOC7) (io), 104 TXD2 (GPIOC6) (io), 105 RXD1 (~{SS0}) (in), 106 TXD1 (MISO0) (io), 107 RXD0 (MOSI0) (io), 108 TXD0 (SCLK0) (io), 109 TA3 (GPIOF3) (io), 110 TA2 (GPIOF2) (io), 111 TA1 (GPIOF1) (io), 112 TA0  (GPIOF0) (io), 113 VDDIO (power), 114 VSSIO (power), 115 VSS (power), 116 VDD (power), 117 GPIOB7 (io), 118 GPIOB6 (io), 119 GPIOB5 (io), 120 GPIOB4 (io), 121 GPIOB3 (io), 122 GPIOB2 (io), 123 GPIOB1 (io), 124 GPIOB0 (io), 125 D0 (GPIOG0) (io), 126 D1 (GPIOG1) (io), 127 D2 (GPIOG2) (io), 128 D3 (GPIOG3) (io)

## DSP56603PV60
designator U?
16-Bit Digital Signal Processor
footprint 918-03_N (Thin QFP, 144-Leads, Body 20x20mm, Pitch 0.5mm, IPC Medium Density)
footprint 918-03_L (Thin QFP, 144-Leads, Body 20x20mm, Pitch 0.5mm, IPC High Density)
footprint 918-03_M (Thin QFP, 144-Leads, Body 20x20mm, Pitch 0.5mm, IPC Low Density)
3D model DSP56603-918-03 (144-Pin Low Profile Quad Flat Pack 0.5 mm Pitch (918-03))
pins: 1 SRD1 (in), 2 STD1 (out), 3 SC02 (io), 4 SC01 (io), 5 ~{DE} (io), 6 PINT/~{NMI} (in), 7 SRD0 (in), 8 VCCS (power), 9 GNDS (power), 10 STD0 (out), 11 SC10 (io), 12 SC00 (io), 13 GPIO0 (io), 14 GPIO1 (io), 15 GPIO2 (io), 16 SCK1 (io), 17 SCK0 (io), 18 VCCQL (power), 19 GNDQ (power), 20 VCCQH (power), 21 ~{HDS}/~{HWR} (io), 22 HRW/~{HRD} (io), 23 ~{HACK}/~{HRRQ} (io), 24 ~{HREQ}/~{HTRQ} (io), 25 VCCS (power), 26 GNDS (power), 27 TIO2 (io), 28 TIO1 (io), 29 TIO0 (io), 30 ~{HCS}/HA10 (io), 31 HA2/HA9 (in), 32 HA1/HA8 (in), 33 HA0/~{HAS} (in), 34 HAD7 (io), 35 HAD6 (io), 36 HAD5 (io), 37 HAD4 (io), 38 VCCH (power), 39 GNDH (power), 40 HAD3 (io), 41 HAD2 (io), 42 HAD1 (io), 43 HAD0 (io), 44 ~{RESET} (in), 45 VCCP (power), 46 PCAP (in), 47 GNDP (power), 48 GNDP1 (power), 49 NC, 50 NC, 51 NC, 52 NC, 53 XTAL, 54 GNDQ (power), 55 EXTAL, 56 VCCQL (power), 57 VCCQH (power), 58 GNDC (power), 59 CLKOUT (out), 60 ~{AT} (out), 61 NC, 62 NC, 63 NC, 64 NC, 65 VCCC (power), 66 GNDC (power), 67 ~{WR} (out), 68 ~{RD} (out), 69 NC, 70 ~{MCS} (out), 71 NC, 72 A0 (out), 73 A1 (out), 74 VCCA (power), 75 GNDA (power), 76 A2 (out), 77 A3 (out), 78 A4 (out), 79 A5 (out), 80 VCCA (power), 81 GNDA (power), 82 A6 (out), 83 A7 (out), 84 A8 (out), 85 A9 (out), 86 VCCA (power), 87 GNDA (power), 88 A10 (out), 89 A11 (out), 90 GNDQ (power), 91 VCCQL (power), 92 A12 (out), 93 A13 (out), 94 A14 (out), 95 VCCQH (power), 96 GNDA (power), 97 A15 (out), 98 NC, 99 NC, 100 D0 (io), 101 D1 (io), 102 D2 (io), 103 VCCD (power), 104 GNDD (power), 105 D3 (io), 106 D4 (io), 107 D5 (io), 108 D6 (io), 109 D7 (io), 110 D8 (io), 111 VCCD (power), 112 GNDD (power), 113 D9 (io), 114 D10 (io), 115 D11 (io), 116 D12 (io), 117 D13 (io), 118 D14 (io), 119 VCCD (power), 120 GNDD (power), 121 D15 (io), 122 D16 (io), 123 D17 (io), 124 D18 (io), 125 D19 (io), 126 VCCQL (power), 127 GNDQ (power), 128 D20 (io), 129 VCCD (power), 130 GNDD (power), 131 D21 (io), 132 D22 (io), 133 D23 (io), 134 MODD (in), 135 MODC (in), 136 MODB (in), 137 MODA (in), 138 ~{TRST} (in), 139 TDO (out), 140 TDI (in), 141 TCK (in), 142 TMS (in), 143 SC12 (io), 144 SC11 (io)

## DSP56852VF120
designator U?
DSP56800E General Purpose 16-Bit Fixed Point DSP
footprint 1224B-01 (BGA, 81-Leads, Body 8x8mm, Pitch 0.8mm)
3D model DSP56852-1224B-01 (81-Ball MAP-Ball Grid Array 0.8 mm Pitch)
pins: A1 ~{IRQA} (in), A2 GPIOC1 (SRXD) (io), A3 SCK (GPIOC2, STCK) (io), A4 VDDIO (power), A5 VSSIO (power), A6 EXTAL, A7 XTAL (io), A8 TDO (out), A9 D15 (MODE C) (io), B1 VSSIO (power), B2 GPIOC0 (STXD) (io), B3 ~{SS} (GPIOC3, STFS) (io), B4 RXD (GPIOE0) (io), B5 VDDA (power), B6 VSSA (power), B7 TDI (in), B8 ~{DE} (io), B9 VDDIO (power), C1 VDDIO (power), C2 ~{IRQB} (in), C3 CS2 (GPIOA2) (io), C4 MISO (GPIOC4, SRCK) (io), C5 MOSI (GPIOC5, SRFS) (io), C6 TCK (in), C7 TMS (in), C8 D14 (MODE B) (io), C9 VSSIO (power), D1 VSS (power), D2 CS0 (GPIOA0) (io), D3 CS1 (GPIOA1) (io), D4 TXD (GPIOE1) (io), D5 ~{RESET} (in), D6 ~{TRST} (in), D7 D12 (io), D8 D11 (io), D9 D13 (MODE A) (io), E1 VDD (power), E2 ~{RD} (out), E3 ~{WR} (out), E4 A0 (hiz), E5 A16 (hiz), E6 D10 (io), E7 D9 (io), E8 D8 (io), E9 VDD (power), F1 A4 (hiz), F2 A1 (hiz), F3 A2 (hiz), F4 A3 (hiz), F5 A14 (hiz), F6 A17 (TIO0) (io), F7 D6 (io), F8 D5 (io), F9 VSS (power), G1 VSSIO (power), G2 A6 (hiz), G3 A5 (hiz), G4 A12 (hiz), G5 A18 (TIO1) (io), G6 D7 (io), G7 D0 (io), G8 D3 (io), G9 VDDIO (power), H1 VDDIO (power), H2 A8 (hiz), H3 A9 (hiz), H4 A11 (hiz), H5 A15 (hiz), H6 A19 (~{CS}3) (hiz), H7 D1 (io), H8 D2 (io), H9 D4 (io), J1 A7 (hiz), J2 A10 (hiz), J3 A13 (hiz), J4 VSS (power), J5 VDD (power), J6 VSSIO (power), J7 VDDIO (power), J8 CLKO (A20) (out), J9 VSSIO (power)

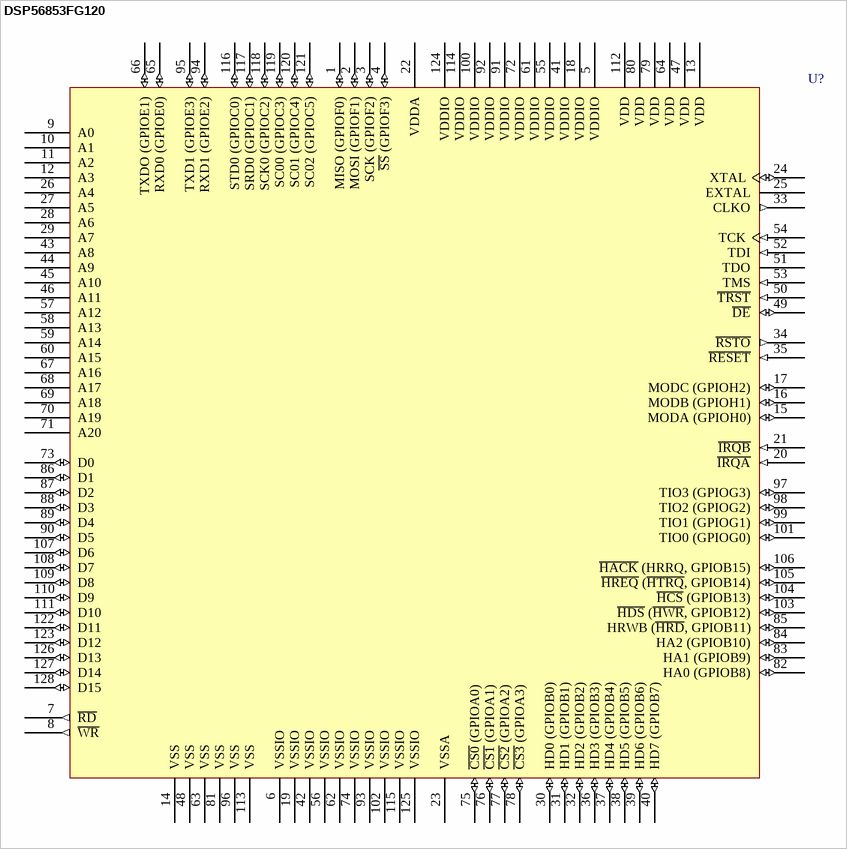
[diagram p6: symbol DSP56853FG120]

## DSP56853FG120
designator U?
DSP56800E General Purpose 16-Bit Fixed Point DSP
footprint 1129-01_N (Thin QFP, 128-Leads, Body 20x14 mm, Pitch 0.5mm, IPC Medium Density)
footprint 1129-01_L (Thin QFP, 128-Leads, Body 20x14 mm, Pitch 0.5mm, IPC High Density)
footprint 1129-01_M (Thin QFP, 128-Leads, Body 20x14 mm, Pitch 0.5mm, IPC Low Density)
3D model DSP56853-1129-01 (128-Pin Thin Quad Flat Pack Rectangular 0.5 mm Pitch)
pins: 1 MISO (GPIOF0) (io), 2 MOSI (GPIOF1) (io), 3 SCK (GPIOF2) (io), 4 ~{SS} (GPIOF3) (io), 5 VDDIO (power), 6 VSSIO (power), 7 ~{RD} (out), 8 ~{WR} (out), 9 A0 (hiz), 10 A1 (hiz), 11 A2 (hiz), 12 A3 (hiz), 13 VDD (power), 14 VSS (power), 15 MODA (GPIOH0) (io), 16 MODB (GPIOH1) (io), 17 MODC (GPIOH2) (io), 18 VDDIO (power), 19 VSSIO (power), 20 ~{IRQA} (in), 21 ~{IRQB} (in), 22 VDDA (power), 23 VSSA (power), 24 XTAL (io), 25 EXTAL, 26 A4 (hiz), 27 A5 (hiz), 28 A6 (hiz), 29 A7 (hiz), 30 HD0 (GPIOB0) (io), 31 HD1 (GPIOB1) (io), 32 HD2 (GPIOB2) (io), 33 CLKO (out), 34 ~{RSTO} (out), 35 ~{RESET} (in), 36 HD3 (GPIOB3) (io), 37 HD4 (GPIOB4) (io), 38 HD5 (GPIOB5) (io), 39 HD6 (GPIOB6) (io), 40 HD7 (GPIOB7) (io), 41 VDDIO (power), 42 VSSIO (power), 43 A8 (hiz), 44 A9 (hiz), 45 A10 (hiz), 46 A11 (hiz), 47 VDD (power), 48 VSS (power), 49 ~{DE} (io), 50 ~{TRST} (in), 51 TDO (hiz), 52 TDI (in), 53 TMS (in), 54 TCK (in), 55 VDDIO (power), 56 VSSIO (power), 57 A12 (hiz), 58 A13 (hiz), 59 A14 (hiz), 60 A15 (hiz), 61 VDDIO (power), 62 VSSIO (power), 63 VSS (power), 64 VDD (power), 65 RXD0 (GPIOE0) (io), 66 TXDO (GPIOE1) (io), 67 A16 (hiz), 68 A17 (hiz), 69 A18 (hiz), 70 A19 (hiz), 71 A20 (hiz), 72 VDDIO (power), 73 D0 (io), 74 VSSIO (power), 75 ~{CS0} (GPIOA0) (io), 76 ~{CS1} (GPIOA1) (io), 77 ~{CS2} (GPIOA2) (io), 78 ~{CS3} (GPIOA3) (io), 79 VDD (power), 80 VDD (power), 81 VSS (power), 82 HA0 (GPIOB8) (io), 83 HA1 (GPIOB9) (io), 84 HA2 (GPIOB10) (io), 85 HRWB (~{HRD}, GPIOB11) (io), 86 D1 (io), 87 D2 (io), 88 D3 (io), 89 D4 (io), 90 D5 (io), 91 VDDIO (power), 92 VDDIO (power), 93 VSSIO (power), 94 RXD1 (GPIOE2) (io), 95 TXD1 (GPIOE3) (io), 96 VSS (power), 97 TIO3 (GPIOG3) (io), 98 TIO2 (GPIOG2) (io), 99 TIO1 (GPIOG1) (io), 100 VDDIO (power), 101 TIO0 (GPIOG0) (io), 102 VSSIO (power), 103 ~{HDS} (~{HWR}, GPIOB12) (io), 104 ~{HCS} (GPIOB13) (io), 105 ~{HREQ} (~{HTRQ}, GPIOB14) (io), 106 ~{HACK} (HRRQ, GPIOB15) (io), 107 D6 (io), 108 D7 (io), 109 D8 (io), 110 D9 (io), 111 D10 (io), 112 VDD (power), 113 VSS (power), 114 VDDIO (power), 115 VSSIO (power), 116 STD0 (GPIOC0) (io), 117 SRD0 (GPIOC1) (io), 118 SCK0 (GPIOC2) (io), 119 SC00 (GPIOC3) (io), 120 SC01 (GPIOC4) (io), 121 SC02 (GPIOC5) (io), 122 D11 (io), 123 D12 (io), 124 VDDIO (power), 125 VSSIO (power), 126 D13 (io), 127 D14 (io), 128 D15 (io)

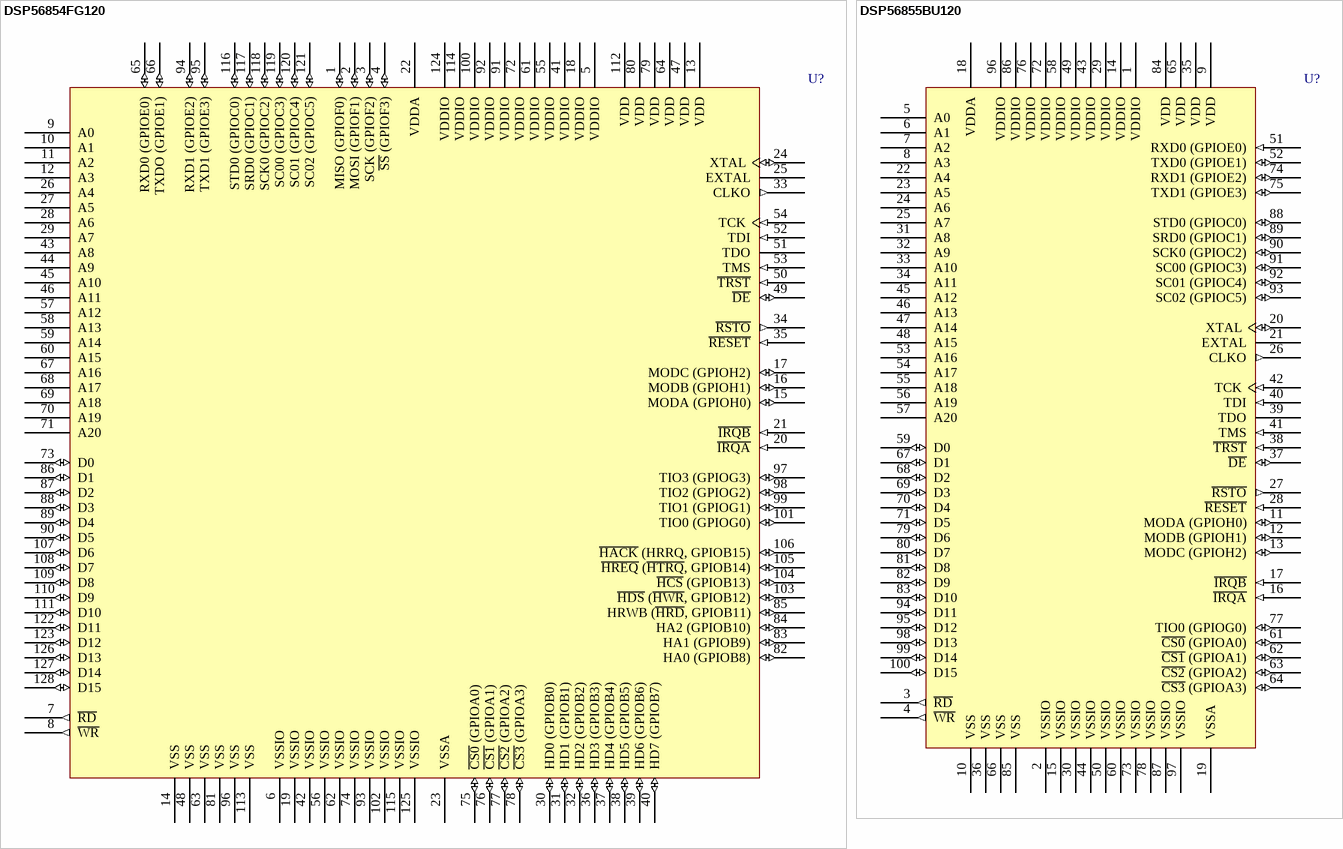
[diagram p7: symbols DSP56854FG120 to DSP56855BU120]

## DSP56854FG120
designator U?
DSP56800E General Purpose 16-Bit Fixed Point DSP
footprint 1129-01_N (Thin QFP, 128-Leads, Body 20x14 mm, Pitch 0.5mm, IPC Medium Density)
footprint 1129-01_L (Thin QFP, 128-Leads, Body 20x14 mm, Pitch 0.5mm, IPC High Density)
footprint 1129-01_M (Thin QFP, 128-Leads, Body 20x14 mm, Pitch 0.5mm, IPC Low Density)
3D model DSP56854-1129-01 (128-Pin Thin Quad Flat Pack Rectangular 0.5 mm Pitch)
pins: 1 MISO (GPIOF0) (io), 2 MOSI (GPIOF1) (io), 3 SCK (GPIOF2) (io), 4 ~{SS} (GPIOF3) (io), 5 VDDIO (power), 6 VSSIO (power), 7 ~{RD} (out), 8 ~{WR} (out), 9 A0 (hiz), 10 A1 (hiz), 11 A2 (hiz), 12 A3 (hiz), 13 VDD (power), 14 VSS (power), 15 MODA (GPIOH0) (io), 16 MODB (GPIOH1) (io), 17 MODC (GPIOH2) (io), 18 VDDIO (power), 19 VSSIO (power), 20 ~{IRQA} (in), 21 ~{IRQB} (in), 22 VDDA (power), 23 VSSA (power), 24 XTAL (io), 25 EXTAL, 26 A4 (hiz), 27 A5 (hiz), 28 A6 (hiz), 29 A7 (hiz), 30 HD0 (GPIOB0) (io), 31 HD1 (GPIOB1) (io), 32 HD2 (GPIOB2) (io), 33 CLKO (out), 34 ~{RSTO} (out), 35 ~{RESET} (in), 36 HD3 (GPIOB3) (io), 37 HD4 (GPIOB4) (io), 38 HD5 (GPIOB5) (io), 39 HD6 (GPIOB6) (io), 40 HD7 (GPIOB7) (io), 41 VDDIO (power), 42 VSSIO (power), 43 A8 (hiz), 44 A9 (hiz), 45 A10 (hiz), 46 A11 (hiz), 47 VDD (power), 48 VSS (power), 49 ~{DE} (io), 50 ~{TRST} (in), 51 TDO (hiz), 52 TDI (in), 53 TMS (in), 54 TCK (in), 55 VDDIO (power), 56 VSSIO (power), 57 A12 (hiz), 58 A13 (hiz), 59 A14 (hiz), 60 A15 (hiz), 61 VDDIO (power), 62 VSSIO (power), 63 VSS (power), 64 VDD (power), 65 RXD0 (GPIOE0) (io), 66 TXDO (GPIOE1) (io), 67 A16 (hiz), 68 A17 (hiz), 69 A18 (hiz), 70 A19 (hiz), 71 A20 (hiz), 72 VDDIO (power), 73 D0 (io), 74 VSSIO (power), 75 ~{CS0} (GPIOA0) (io), 76 ~{CS1} (GPIOA1) (io), 77 ~{CS2} (GPIOA2) (io), 78 ~{CS3} (GPIOA3) (io), 79 VDD (power), 80 VDD (power), 81 VSS (power), 82 HA0 (GPIOB8) (io), 83 HA1 (GPIOB9) (io), 84 HA2 (GPIOB10) (io), 85 HRWB (~{HRD}, GPIOB11) (io), 86 D1 (io), 87 D2 (io), 88 D3 (io), 89 D4 (io), 90 D5 (io), 91 VDDIO (power), 92 VDDIO (power), 93 VSSIO (power), 94 RXD1 (GPIOE2) (io), 95 TXD1 (GPIOE3) (io), 96 VSS (power), 97 TIO3 (GPIOG3) (io), 98 TIO2 (GPIOG2) (io), 99 TIO1 (GPIOG1) (io), 100 VDDIO (power), 101 TIO0 (GPIOG0) (io), 102 VSSIO (power), 103 ~{HDS} (~{HWR}, GPIOB12) (io), 104 ~{HCS} (GPIOB13) (io), 105 ~{HREQ} (~{HTRQ}, GPIOB14) (io), 106 ~{HACK} (HRRQ, GPIOB15) (io), 107 D6 (io), 108 D7 (io), 109 D8 (io), 110 D9 (io), 111 D10 (io), 112 VDD (power), 113 VSS (power), 114 VDDIO (power), 115 VSSIO (power), 116 STD0 (GPIOC0) (io), 117 SRD0 (GPIOC1) (io), 118 SCK0 (GPIOC2) (io), 119 SC00 (GPIOC3) (io), 120 SC01 (GPIOC4) (io), 121 SC02 (GPIOC5) (io), 122 D11 (io), 123 D12 (io), 124 VDDIO (power), 125 VSSIO (power), 126 D13 (io), 127 D14 (io), 128 D15 (io)

## DSP56855BU120
designator U?
DSP56800E General Purpose 16-Bit Fixed Point DSP
footprint 842F-01_N (Thin QFP, 100-Leads, Body 14x14mm, Pitch 0.5mm, IPC Medium Density)
footprint 842F-01_L (Thin QFP, 100-Leads, Body 14x14mm, Pitch 0.5mm, IPC High Density)
footprint 842F-01_M (Thin QFP, 100-Leads, Body 14x14mm, Pitch 0.5mm, IPC Low Density)
3D model DSP56855-842F-01 (100-Pin Thin Quad Flat Pack 0.5 mm Pitch)
pins: 1 VDDIO (power), 2 VSSIO (power), 3 ~{RD} (out), 4 ~{WR} (out), 5 A0 (hiz), 6 A1 (hiz), 7 A2 (hiz), 8 A3 (hiz), 9 VDD (power), 10 VSS (power), 11 MODA (GPIOH0) (io), 12 MODB (GPIOH1) (io), 13 MODC (GPIOH2) (io), 14 VDDIO (power), 15 VSSIO (power), 16 ~{IRQA} (in), 17 ~{IRQB} (in), 18 VDDA (power), 19 VSSA (power), 20 XTAL (io), 21 EXTAL, 22 A4 (hiz), 23 A5 (hiz), 24 A6 (hiz), 25 A7 (hiz), 26 CLKO (out), 27 ~{RSTO} (out), 28 ~{RESET} (in), 29 VDDIO (power), 30 VSSIO (power), 31 A8 (hiz), 32 A9 (hiz), 33 A10 (hiz), 34 A11 (hiz), 35 VDD (power), 36 VSS (power), 37 ~{DE} (io), 38 ~{TRST} (in), 39 TDO (hiz), 40 TDI (in), 41 TMS (in), 42 TCK (in), 43 VDDIO (power), 44 VSSIO (power), 45 A12 (hiz), 46 A13 (hiz), 47 A14 (hiz), 48 A15 (hiz), 49 VDDIO (power), 50 VSSIO (power), 51 RXD0 (GPIOE0) (in), 52 TXD0 (GPIOE1) (io), 53 A16 (hiz), 54 A17 (hiz), 55 A18 (hiz), 56 A19 (hiz), 57 A20 (hiz), 58 VDDIO (power), 59 D0 (io), 60 VSSIO (power), 61 ~{CS0} (GPIOA0) (io), 62 ~{CS1} (GPIOA1) (io), 63 ~{CS2} (GPIOA2) (io), 64 ~{CS3} (GPIOA3) (io), 65 VDD (power), 66 VSS (power), 67 D1 (io), 68 D2 (io), 69 D3 (io), 70 D4 (io), 71 D5 (io), 72 VDDIO (power), 73 VSSIO (power), 74 RXD1 (GPIOE2) (io), 75 TXD1 (GPIOE3) (io), 76 VDDIO (power), 77 TIO0 (GPIOG0) (io), 78 VSSIO (power), 79 D6 (io), 80 D7 (io), 81 D8 (io), 82 D9 (io), 83 D10 (io), 84 VDD (power), 85 VSS (power), 86 VDDIO (power), 87 VSSIO (power), 88 STD0 (GPIOC0) (io), 89 SRD0 (GPIOC1) (io), 90 SCK0 (GPIOC2) (io), 91 SC00 (GPIOC3) (io), 92 SC01 (GPIOC4) (io), 93 SC02 (GPIOC5) (io), 94 D11 (io), 95 D12 (io), 96 VDDIO (power), 97 VSSIO (power), 98 D13 (io), 99 D14 (io), 100 D15 (io)

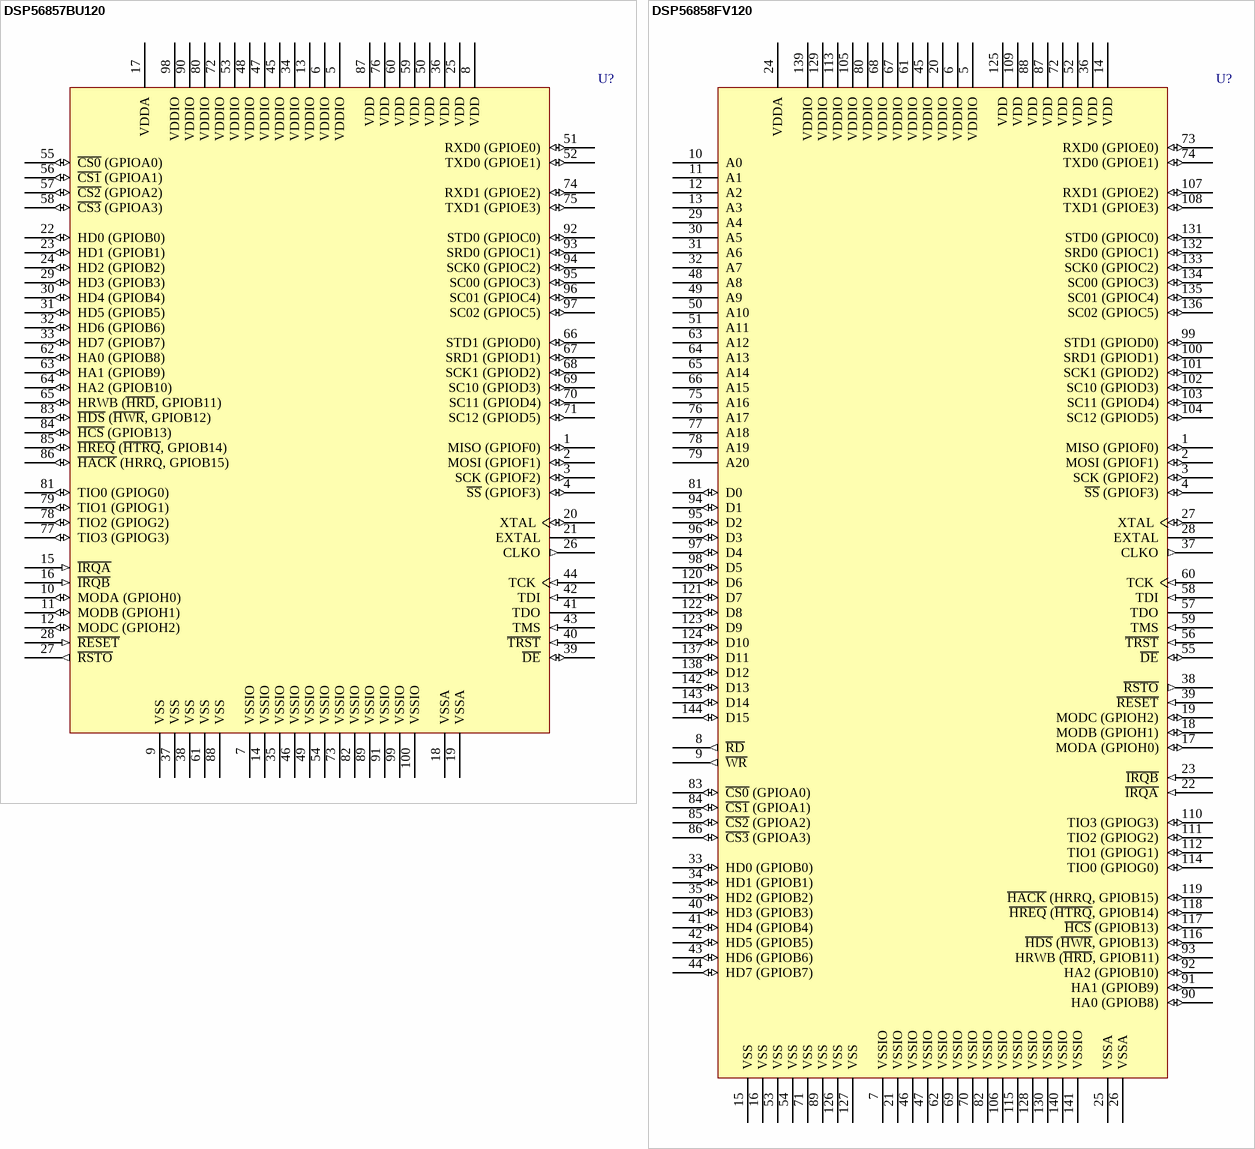
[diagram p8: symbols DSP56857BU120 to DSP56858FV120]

## DSP56857BU120
designator U?
DSP56800E General Purpose 16-Bit Fixed Point DSP
footprint 842F-01_N (Thin QFP, 100-Leads, Body 14x14mm, Pitch 0.5mm, IPC Medium Density)
footprint 842F-01_L (Thin QFP, 100-Leads, Body 14x14mm, Pitch 0.5mm, IPC High Density)
footprint 842F-01_M (Thin QFP, 100-Leads, Body 14x14mm, Pitch 0.5mm, IPC Low Density)
3D model DSP56857-842F-01 (100-Pin Thin Quad Flat Pack 0.5 mm Pitch)
pins: 1 MISO (GPIOF0) (io), 2 MOSI (GPIOF1) (io), 3 SCK (GPIOF2) (io), 4 ~{SS} (GPIOF3) (io), 5 VDDIO (power), 6 VDDIO (power), 7 VSSIO (power), 8 VDD (power), 9 VSS (power), 10 MODA (GPIOH0) (io), 11 MODB (GPIOH1) (io), 12 MODC (GPIOH2) (io), 13 VDDIO (power), 14 VSSIO (power), 15 ~{IRQA} (in), 16 ~{IRQB} (in), 17 VDDA (power), 18 VSSA (power), 19 VSSA (power), 20 XTAL (io), 21 EXTAL, 22 HD0 (GPIOB0) (io), 23 HD1 (GPIOB1) (io), 24 HD2 (GPIOB2) (io), 25 VDD (power), 26 CLKO (out), 27 ~{RSTO} (out), 28 ~{RESET} (in), 29 HD3 (GPIOB3) (io), 30 HD4 (GPIOB4) (io), 31 HD5 (GPIOB5) (io), 32 HD6 (GPIOB6) (io), 33 HD7 (GPIOB7) (io), 34 VDDIO (power), 35 VSSIO (power), 36 VDD (power), 37 VSS (power), 38 VSS (power), 39 ~{DE} (io), 40 ~{TRST} (in), 41 TDO (hiz), 42 TDI (in), 43 TMS (in), 44 TCK (in), 45 VDDIO (power), 46 VSSIO (power), 47 VDDIO (power), 48 VDDIO (power), 49 VSSIO (power), 50 VDD (power), 51 RXD0 (GPIOE0) (io), 52 TXD0 (GPIOE1) (io), 53 VDDIO (power), 54 VSSIO (power), 55 ~{CS0} (GPIOA0) (io), 56 ~{CS1} (GPIOA1) (io), 57 ~{CS2} (GPIOA2) (io), 58 ~{CS3} (GPIOA3) (io), 59 VDD (power), 60 VDD (power), 61 VSS (power), 62 HA0 (GPIOB8) (io), 63 HA1 (GPIOB9) (io), 64 HA2 (GPIOB10) (io), 65 HRWB (~{HRD}, GPIOB11) (io), 66 STD1 (GPIOD0) (io), 67 SRD1 (GPIOD1) (io), 68 SCK1 (GPIOD2) (io), 69 SC10 (GPIOD3) (io), 70 SC11 (GPIOD4) (io), 71 SC12 (GPIOD5) (io), 72 VDDIO (power), 73 VSSIO (power), 74 RXD1 (GPIOE2) (io), 75 TXD1 (GPIOE3) (io), 76 VDD (power), 77 TIO3 (GPIOG3) (io), 78 TIO2 (GPIOG2) (io), 79 TIO1 (GPIOG1) (io), 80 VDDIO (power), 81 TIO0 (GPIOG0) (io), 82 VSSIO (power), 83 ~{HDS} (~{HWR}, GPIOB12) (io), 84 ~{HCS} (GPIOB13) (io), 85 ~{HREQ} (~{HTRQ}, GPIOB14) (io), 86 ~{HACK} (HRRQ, GPIOB15) (io), 87 VDD (power), 88 VSS (power), 89 VSSIO (power), 90 VDDIO (power), 91 VSSIO (power), 92 STD0 (GPIOC0) (io), 93 SRD0 (GPIOC1) (io), 94 SCK0 (GPIOC2) (io), 95 SC00 (GPIOC3) (io), 96 SC01 (GPIOC4) (io), 97 SC02 (GPIOC5) (io), 98 VDDIO (power), 99 VSSIO (power), 100 VSSIO (power)

## DSP56858FV120
designator U?
DSP56800E General Purpose 16-Bit Fixed Point DSP
footprint 918-03_N (Thin QFP, 144-Leads, Body 20x20mm, Pitch 0.5mm, IPC Medium Density)
footprint 918-03_L (Thin QFP, 144-Leads, Body 20x20mm, Pitch 0.5mm, IPC High Density)
footprint 918-03_M (Thin QFP, 144-Leads, Body 20x20mm, Pitch 0.5mm, IPC Low Density)
3D model DSP56858-918-03 (144-Pin Low Profile Quad Flat Pack 0.5 mm Pitch (918-03))
pins: 1 MISO (GPIOF0) (io), 2 MOSI (GPIOF1) (io), 3 SCK (GPIOF2) (io), 4 ~{SS} (GPIOF3) (io), 5 VDDIO (power), 6 VDDIO (power), 7 VSSIO (power), 8 ~{RD} (out), 9 ~{WR} (out), 10 A0 (hiz), 11 A1 (hiz), 12 A2 (hiz), 13 A3 (hiz), 14 VDD (power), 15 VSS (power), 16 VSS (power), 17 MODA (GPIOH0) (io), 18 MODB (GPIOH1) (io), 19 MODC (GPIOH2) (io), 20 VDDIO (power), 21 VSSIO (power), 22 ~{IRQA} (in), 23 ~{IRQB} (in), 24 VDDA (power), 25 VSSA (power), 26 VSSA (power), 27 XTAL (io), 28 EXTAL, 29 A4 (hiz), 30 A5 (hiz), 31 A6 (hiz), 32 A7 (hiz), 33 HD0 (GPIOB0) (io), 34 HD1 (GPIOB1) (io), 35 HD2 (GPIOB2) (io), 36 VDD (power), 37 CLKO (out), 38 ~{RSTO} (out), 39 ~{RESET} (in), 40 HD3 (GPIOB3) (io), 41 HD4 (GPIOB4) (io), 42 HD5 (GPIOB5) (io), 43 HD6 (GPIOB6) (io), 44 HD7 (GPIOB7) (io), 45 VDDIO (power), 46 VSSIO (power), 47 VSSIO (power), 48 A8 (hiz), 49 A9 (hiz), 50 A10 (hiz), 51 A11 (hiz), 52 VDD (power), 53 VSS (power), 54 VSS (power), 55 ~{DE} (io), 56 ~{TRST} (in), 57 TDO (hiz), 58 TDI (in), 59 TMS (in), 60 TCK (in), 61 VDDIO (power), 62 VSSIO (power), 63 A12 (hiz), 64 A13 (hiz), 65 A14 (hiz), 66 A15 (hiz), 67 VDDIO (power), 68 VDDIO (power), 69 VSSIO (power), 70 VSSIO (power), 71 VSS (power), 72 VDD (power), 73 RXD0 (GPIOE0) (io), 74 TXD0 (GPIOE1) (io), 75 A16 (hiz), 76 A17 (hiz), 77 A18 (hiz), 78 A19 (hiz), 79 A20 (hiz), 80 VDDIO (power), 81 D0 (io), 82 VSSIO (power), 83 ~{CS0} (GPIOA0) (io), 84 ~{CS1} (GPIOA1) (io), 85 ~{CS2} (GPIOA2) (io), 86 ~{CS3} (GPIOA3) (io), 87 VDD (power), 88 VDD (power), 89 VSS (power), 90 HA0 (GPIOB8) (io), 91 HA1 (GPIOB9) (io), 92 HA2 (GPIOB10) (io), 93 HRWB (~{HRD}, GPIOB11) (io), 94 D1 (io), 95 D2 (io), 96 D3 (io), 97 D4 (io), 98 D5 (io), 99 STD1 (GPIOD0) (io), 100 SRD1 (GPIOD1) (io), 101 SCK1 (GPIOD2) (io), 102 SC10 (GPIOD3) (io), 103 SC11 (GPIOD4) (io), 104 SC12 (GPIOD5) (io), 105 VDDIO (power), 106 VSSIO (power), 107 RXD1 (GPIOE2) (io), 108 TXD1 (GPIOE3) (io), 109 VDD (power), 110 TIO3 (GPIOG3) (io), 111 TIO2 (GPIOG2) (io), 112 TIO1 (GPIOG1) (io), 113 VDDIO (power), 114 TIO0 (GPIOG0) (io), 115 VSSIO (power), 116 ~{HDS} (~{HWR}, GPIOB13) (io), 117 ~{HCS} (GPIOB13) (io), 118 ~{HREQ} (~{HTRQ}, GPIOB14) (io), 119 ~{HACK} (HRRQ, GPIOB15) (io), 120 D6 (io), 121 D7 (io), 122 D8 (io), 123 D9 (io), 124 D10 (io), 125 VDD (power), 126 VSS (power), 127 VSS (power), 128 VSSIO (power), 129 VDDIO (power), 130 VSSIO (power), 131 STD0 (GPIOC0) (io), 132 SRD0 (GPIOC1) (io), 133 SCK0 (GPIOC2) (io), 134 SC00 (GPIOC3) (io), 135 SC01 (GPIOC4) (io), 136 SC02 (GPIOC5) (io), 137 D11 (io), 138 D12 (io), 139 VDDIO (power), 140 VSSIO (power), 141 VSSIO (power), 142 D13 (io), 143 D14 (io), 144 D15 (io)

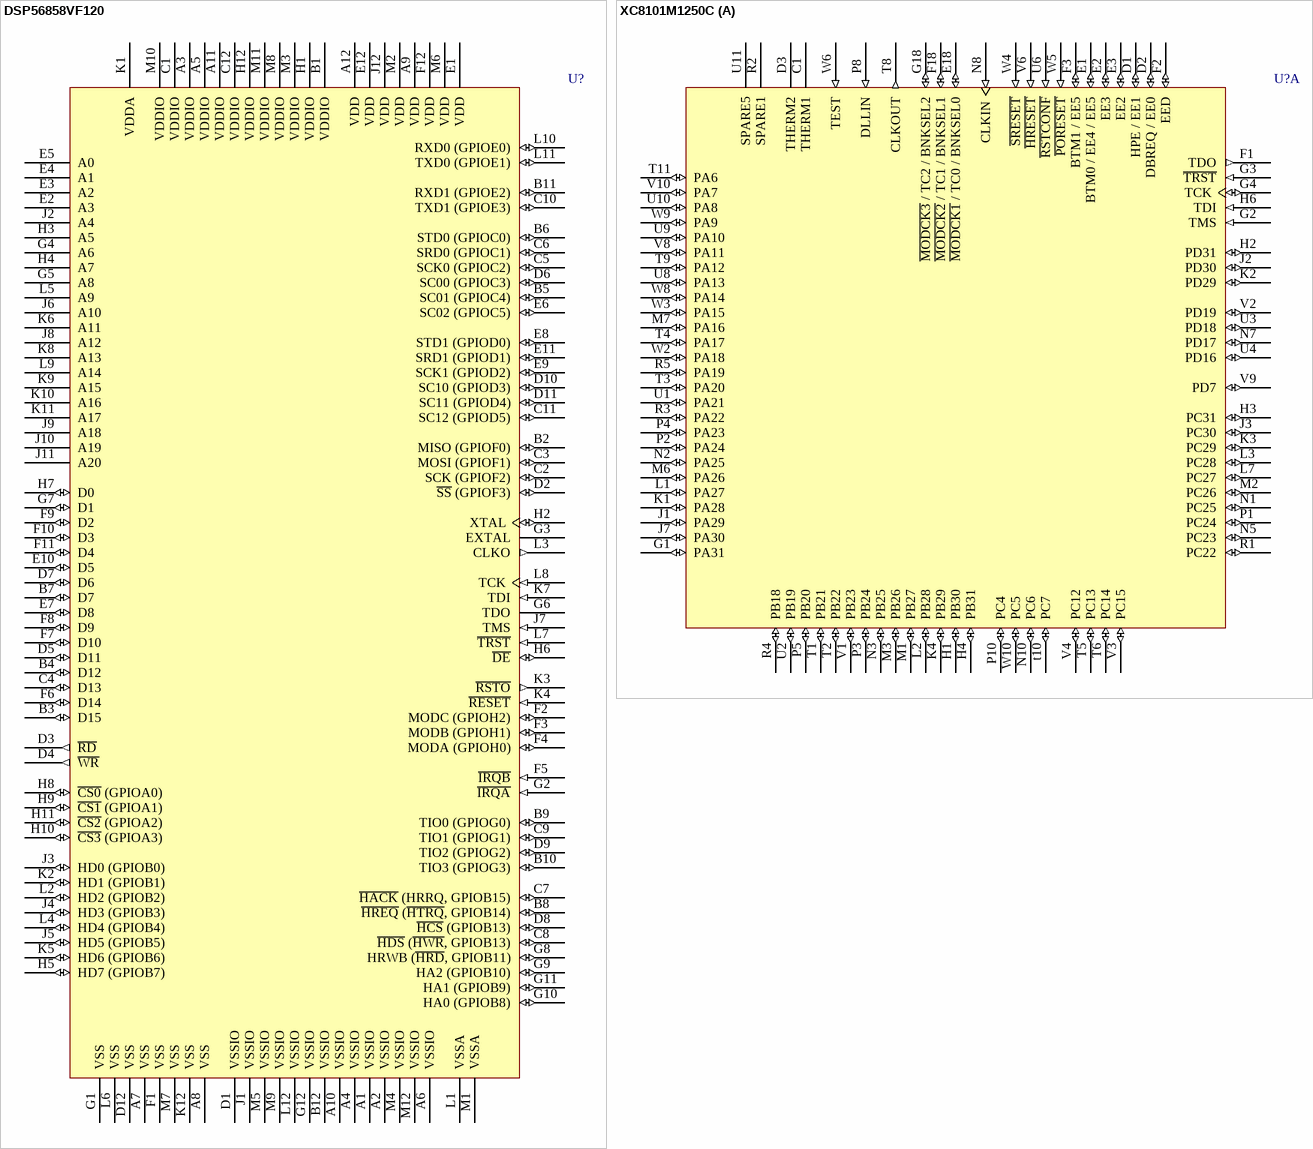
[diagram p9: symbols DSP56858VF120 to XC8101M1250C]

## DSP56858VF120
designator U?
DSP56800E General Purpose 16-Bit Fixed Point DSP
footprint 1242A-03 (BGA, 144-Leads, Body 13x13mm, Pitch 1mm)
3D model DSP56858-1242A-03 (144-Ball MAP-Ball Grid Array 1 mm Pitch)
pins: A1 VSSIO (power), A2 VSSIO (power), A3 VDDIO (power), A4 VSSIO (power), A5 VDDIO (power), A6 VSSIO (power), A7 VSS (power), A8 VSS (power), A9 VDD (power), A10 VSSIO (power), A11 VDDIO (power), A12 VDD (power), B1 VDDIO (power), B2 MISO (GPIOF0) (io), B3 D15 (io), B4 D12 (io), B5 SC01 (GPIOC4) (io), B6 STD0 (GPIOC0) (io), B7 D7 (io), B8 ~{HREQ} (~{HTRQ}, GPIOB14) (io), B9 TIO0 (GPIOG0) (io), B10 TIO3 (GPIOG3) (io), B11 RXD1 (GPIOE2) (io), B12 VSSIO (power), C1 VDDIO (power), C2 SCK (GPIOF2) (io), C3 MOSI (GPIOF1) (io), C4 D13 (io), C5 SCK0 (GPIOC2) (io), C6 SRD0 (GPIOC1) (io), C7 ~{HACK} (HRRQ, GPIOB15) (io), C8 ~{HDS} (~{HWR}, GPIOB13) (io), C9 TIO1 (GPIOG1) (io), C10 TXD1 (GPIOE3) (io), C11 SC12 (GPIOD5) (io), C12 VDDIO (power), D1 VSSIO (power), D2 ~{SS} (GPIOF3) (io), D3 ~{RD} (out), D4 ~{WR} (out), D5 D11 (io), D6 SC00 (GPIOC3) (io), D7 D6 (io), D8 ~{HCS} (GPIOB13) (io), D9 TIO2 (GPIOG2) (io), D10 SC10 (GPIOD3) (io), D11 SC11 (GPIOD4) (io), D12 VSS (power), E1 VDD (power), E2 A3 (hiz), E3 A2 (hiz), E4 A1 (hiz), E5 A0 (hiz), E6 SC02 (GPIOC5) (io), E7 D8 (io), E8 STD1 (GPIOD0) (io), E9 SCK1 (GPIOD2) (io), E10 D5 (io), E11 SRD1 (GPIOD1) (io), E12 VDD (power), F1 VSS (power), F2 MODC (GPIOH2) (io), F3 MODB (GPIOH1) (io), F4 MODA (GPIOH0) (io), F5 ~{IRQB} (in), F6 D14 (io), F7 D10 (io), F8 D9 (io), F9 D2 (io), F10 D3 (io), F11 D4 (io), F12 VDD (power), G1 VSS (power), G2 ~{IRQA} (in), G3 EXTAL, G4 A6 (hiz), G5 A8 (hiz), G6 TDO (hiz), G7 D1 (io), G8 HRWB (~{HRD}, GPIOB11) (io), G9 HA2 (GPIOB10) (io), G10 HA0 (GPIOB8) (io), G11 HA1 (GPIOB9) (io), G12 VSSIO (power), H1 VDDIO (power), H2 XTAL (io), H3 A5 (hiz), H4 A7 (hiz), H5 HD7 (GPIOB7) (io), H6 ~{DE} (io), H7 D0 (io), H8 ~{CS0} (GPIOA0) (io), H9 ~{CS1} (GPIOA1) (io), H10 ~{CS3} (GPIOA3) (io), H11 ~{CS2} (GPIOA2) (io), H12 VDDIO (power), J1 VSSIO (power), J2 A4 (hiz), J3 HD0 (GPIOB0) (io), J4 HD3 (GPIOB3) (io), J5 HD5 (GPIOB5) (io), J6 A10 (hiz), J7 TMS (in), J8 A12 (hiz), J9 A18 (hiz), J10 A19 (hiz), J11 A20 (hiz), J12 VDD (power), K1 VDDA (power), K2 HD1 (GPIOB1) (io), K3 ~{RSTO} (out), K4 ~{RESET} (in), K5 HD6 (GPIOB6) (io), K6 A11 (hiz), K7 TDI (in), K8 A13 (hiz), K9 A15 (hiz), K10 A16 (hiz), K11 A17 (hiz), K12 VSS (power), L1 VSSA (power), L2 HD2 (GPIOB2) (io), L3 CLKO (out), L4 HD4 (GPIOB4) (io), L5 A9 (hiz), L6 VSS (power), L7 ~{TRST} (in), L8 TCK (in), L9 A14 (hiz), L10 RXD0 (GPIOE0) (io), L11 TXD0 (GPIOE1) (io), L12 VSSIO (power), M1 VSSA (power), M2 VDD (power), M3 VDDIO (power), M4 VSSIO (power), M5 VSSIO (power), M6 VDD (power), M7 VSS (power), M8 VDDIO (power), M9 VSSIO (power), M10 VDDIO (power), M11 VDDIO (power), M12 VSSIO (power)

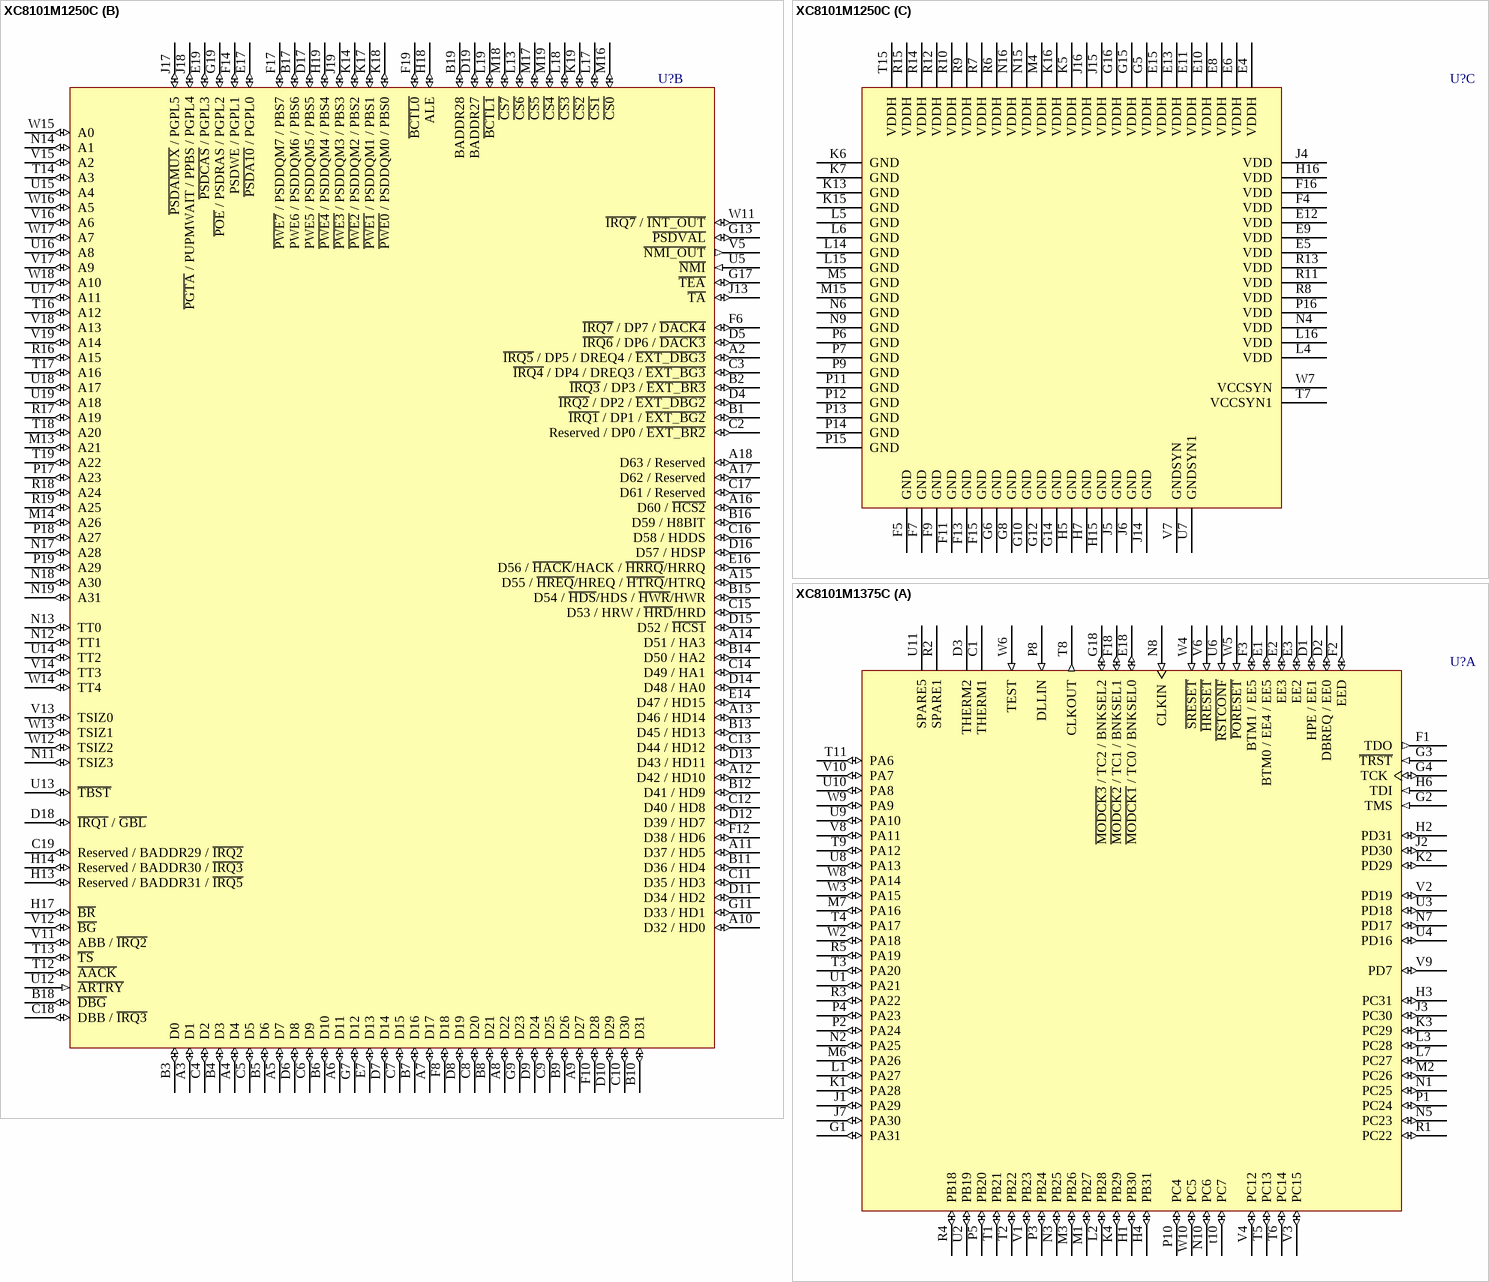
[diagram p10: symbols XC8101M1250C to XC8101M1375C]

## XC8101M1250C
designator U?
MSC8100 Family Very High Performance 16-Bit Fixed Point DSP; PinDescriptions: Alternate pin usages may be listed in Pin Description fields.
footprint 1169-01 (BGA, 332-Leads, Body 17x17mm, Pitch 0.8mm)
3D model XC8101-1169-01 (332-Ball FC-P Ball Grid Array 0.8 mm Pitch)
part A pins: C1 THERM1, D1 HPE / EE1 (io), D2 DBREQ / EE0 (io), D3 THERM2, E1 BTM0 / EE4 / EE5 (io), E2 EE3 (io), E3 EE2 (io), E18 ~{MODCK1} / TC0 / BNKSEL0 (io), F1 TDO (out), F2 EED (io), F3 BTM1 / EE5 (io), F18 ~{MODCK2} / TC1 / BNKSEL1 (io), G1 PA31 (io) "/ FCC1:UTOPIA8:TXENB / FCC1:MII:COL", G2 TMS (in), G3 ~{TRST} (in), G4 TCK (io), G18 ~{MODCK3} / TC2 / BNKSEL2 (io), H1 PB30 (io) "/ FCC2:MII:RX_DV / SCC2:TXD / TDBM2:L1RXD", H2 PD31 (io) "/ SCC1:RXD / DRACK1 / DONE1", H3 PC31 (io) "/ BRG1O / CLK1 / TGATE1", H4 PB31 (io) "/ FCC2:MII:TX_ER / SCC2:RXD / TDMB2:L1TXD", H6 TDI (in), J1 PA29 (io) "/ FCC1:UTOPIA8:TXSOC / FCC1:MII:TX_ER", J2 PD30 (io) "/ SCC1:TXD / DMA:DRACK2/DONE2", J3 PC30 (io) "/ EXT1 / BRG2O / CLK2 / TOUT1", J7 PA30 (io) "/ FCC1:UTOPIA8:TXCLAV / FCC1:UTOPIA8:TXCLAV0 / FCC1:MII:CRS / FCC1:HDLC and transparent:RTS", K1 PA28 (io) "/ FCC1:UTOPIA8:RXENB / FCC1:MII:TX_EN", K2 PD29 (io) "/ FCC1:UTOPIA8:RXADDR3 / FCC1:UTOPIA8:RXCLAV2 / SCC1:RTS/TENA", K3 PC29 (io) "/ SCC1:CTS / SCC1:CLSN / BRG3O / CLK3 / TIN2", K4 PB29 (io) "/ FCC2:MII:TX_EN / TDMB2:L1RSYNC", L1 PA27 (io) "/ FCC1:UTOPIA8:RXSOC / FCC1:MII:RX_DV", L2 PB28 (io) "/ FCC2:RX_ER / FCC2:HDLC:RTS / SCC2:RTS/TENA / TDMB2:L1TSYNC", L3 PC28 (io) "/ SCC2:CTS/CLSN / BRG4O / CLK4 / TIN1/TOUT2", L7 PC27 (io) "/ CLK5 / BRG5O / TGATE2", M1 PB27 (io) "/ FCC2:MII:COL / TDMC2:L1TXD", M2 PC26 (io) "/ TMCLK / BRG6O / CLK6 / TOUT3", M3 PB26 (io) "/ FCC2:MII:CRS / TDMC2:L1RXD", M6 PA26 (io) "/ FCC1:UTOPIA8:RXCLAV / FCC1:UTOPIA8:RXCLAV0 / FCC1:MII:RX_ER", M7 PA16 (io) "/ FCC1:UTOPIA8:RXD6 / FCC1:MII and HDLC nibble:RXD1", N1 PC25 (io) "/ DMA:DACK2 / BRG7O / CLK7 / TIN4", N2 PA25 (io) "/ FCC1:UTOPIA8:TXD0 / SDMA:MSNUM0", N3 PB25 (io) "/ FCC2:MII and HDLC nibble:TXD3 / TDMA1:nibble:L1TXD3 / TDMC2:L1TSYNC/GRANT", N5 PC23 (io) "/ EXT2 / DMA:DACK1 / CLK9", N7 PD17 (io) "/ FCC1:UTOPIA8:RXPRTY / SPI:SPIMOSI / BRG2O", N8 CLKIN (in), N10 PC6 (io) "/ FCC1:UTOPIA8:RXADDR2 / FCC1:UTOPIA8:RXADDR2/RXCLAV1 / FCC1:CD / SI2:LIST2", P1 PC24 (io) "/ DMA:DREQ2 / BRG8O / CLK8 / TIN3/TOUT4", P2 PA24 (io) "/ FCC1:UTOPIA8:TXD1 / SDMA:MSNUM1", P3 PB24 (io) "/ FCC2:MII and HDLC nibble:TXD3 / TDMA1:nibble:L1RXD3 / TDMC2:L1RSYNC", P4 PA23 (io) "/ FCC1:UTOPIA8:TXD2", P5 PB20 (io) "/ FCC2:MII and HDLC nibble:RXD1 / TDMA1:nibble:L1TXD1 / TDMD2:L1RSYNC", P8 DLLIN (in), P10 PC4 (io) "/ FCC2:CD / SMC1:SMRXD / SI2:LIST4", R1 PC22 (io) "/ SI1:LIST1 / DREQ1 / CLK10", R2 SPARE1, R3 PA22 (io) "/ FCC1:UTOPIA8:TXD3", R4 PB18 (io) "/ FCC2:MII and HDLC nibble:RXD3 / I2C:SCL", R5 PA19 (io) "/ FCC1:UTOPIA8:TXD6 / FCC1:MII and HDLC nibble:TXD1", T1 PB21 (io) "/ FCC2:MII and HDLC nibble:RXD0 / FCC2:transparent and HDLC serial:RXD /TDMA1:nibble:L1TXD2 / TDMD2:L1TSYNC/GRANT", T2 PB22 (io) "/ FCC2:MII and HDLC nibble TXD0 / FCC2:transparent and HDLC serial TXD /TDMA1:nibble L1RXD1 / TDMD2:L1RXD", T3 PA20 (io) "/ FCC1:UTOPIA8 TXD5 / FCC1:MII and HDLC nibble TXD2", T4 PA17 (io) "/ FCC1:UTOPIA8 RXD7 / FCC1:MII and HDLC nibble RXD0 / FCC1:transparent and HDLC serial RXD", T5 PC13 (io) "/ FCC1:UTOPIA8:TXADDR1 / SCC2:CTS/CLSN / SI1:LIST4", T6 PC14 (io) "/ FCC1:UTOPIA8:RXADDR0 / SCC1:CD/RENA / SI1:LIST2", T8 CLKOUT (out), T9 PA12 (io) "/ FCC1:UTOPIA8:RXD2 / SDMA:MSNUM3", t10 PC7 (io) "/ FCC1:UTOPIA8:TXADDR2 / FCC1:UTOPIA8:TXADDR2/TXCLAV1 / FCC1:CTS / SI1:LIST1", T11 PA6 (io) "/ TDMA1:L2RSYNC", U1 PA21 (io) "/ FCC1:TXD4 / FCC1:MII and HDLC nibble TXD3", U2 PB19 (io) "/ FCC2:MII and HDLC nibble RXD2 / I2C:SDA", U3 PD18 (io) "/ FCC1:UTOPIA8:RXADDR4 / FCC1:UTOPIA8:RXCLAV3 / SPI:SPICLK", U4 PD16 (io) "/ FCC1:UTOPIA8:TXPRTY / SPI:SPIMISO", U6 ~{RSTCONF} (in), U8 PA13 (io) "/ FCC1:UTOPIA8:RXD3 / SDMA:MSNUM2", U9 PA10 (io) "/ FCC1:UTOPIA8:RXD0 / SDMA:MSNUM5", U10 PA8 (io) "/ SMC2:SMRXD / TDMA1:serial L1RXD / TDMA1:nibble L1RXD0", U11 SPARE5, V1 PB23 (io) "/ FCC2:MII and HDLC nibble:TXD1 / TDMA1:nibble:L1RXD2 / TDMD2:L1TXD", V2 PD19 (io) "/ FCC1:UTOPIA8:TXADDR4 / FCC1:UTOPIA:TXCLAV3 / SPI:SPISEL / BRG1O", V3 PC15 (io) "/ FCC1:UTOPIA8:TXADDR0 / SCC1:CTS/CLSN / SMC2:SMTXD", V4 PC12 (io) "/ FCC1:UTOPIA8:RXADDR1 / SCC2:CD/RENA / SI1:LIST3", V6 ~{HRESET} (in), V8 PA11 (io) "/ FCC1:UTOPIA8:RXD1 / SDMA:MSNUM4", V9 PD7 (io) "/ FCC1:UTOPIA8:TXADDR3 / FCC1:UTOPIA8:TXCLAV2 / SMC1:SMSYN", V10 PA7 (io) "/ SMC2:SMSYN / TDMA1:L1TSYNC/GRANT", W2 PA18 (io) "/ FCC1:UTOPIA8:TXD7 / FCC1:MII and HDLC nibble:TXD0 / FCC1:transparent and HDLC serial:TXD", W3 PA15 (io) "/ FCC1:UTOPIA8:RXD5 / FCC1:MII and HDLC nibble:RXD2", W4 ~{SRESET} (in), W5 ~{PORESET} (in), W6 TEST (in), W8 PA14 (io) "/ FCC1:UTOPIA8 RXD4 / FCC1:MII and HDLC nibble:RXD3", W9 PA9 (io) "/ SMC2:SMTXD / TDMA1:serial:L1TXD /TDMA1:nibble:L1TXD0", W10 PC5 (io) "/ FCC2:CTS / SMC1:SMTXD / SI2:LIST3"
part B pins: A2 ~{IRQ5} / DP5 / DREQ4 / ~{EXT_DBG3} (io), A3 D1 (io), A4 D4 (io), A5 D7 (io), A6 D11 (io), A7 D17 (io), A8 D22 (io), A9 D27 (io), A10 D32 / HD0 (io), A11 D37 / HD5 (io), A12 D42 / HD10 (io), A13 D46 / HD14 (io), A14 D51 / HA3 (io), A15 D55 / ~{HREQ}/HREQ / ~{HTRQ}/HTRQ (io), A16 D60 / ~{HCS2} (io), A17 D62 / Reserved (io), A18 D63 / Reserved (io), B1 ~{IRQ1} / DP1 / ~{EXT_BG2} (io), B2 ~{IRQ3} / DP3 / ~{EXT_BR3} (io), B3 D0 (io), B4 D3 (io), B5 D6 (io), B6 D10 (io), B7 D16 (io), B8 D21 (io), B9 D26 (io), B10 D31 (io), B11 D36 / HD4 (io), B12 D41 / HD9 (io), B13 D45 / HD13 (io), B14 D50 / HA2 (io), B15 D54 / ~{HDS}/HDS / ~{HWR}/HWR (io), B16 D59 / H8BIT (io), B17 PWE6 / PSDDQM6 / PBS6 (io), B18 ~{DBG} (io), B19 BADDR28 (io), C2 Reserved / DP0 / ~{EXT_BR2} (io), C3 ~{IRQ4} / DP4 / DREQ3 / ~{EXT_BG3} (io), C4 D2 (io), C5 D5 (io), C6 D9 (io), C7 D15 (io), C8 D20 (io), C9 D25 (io), C10 D30 (io), C11 D35 / HD3 (io), C12 D40 / HD8 (io), C13 D44 / HD12 (io), C14 D49 / HA1 (io), C15 D53 / HRW / ~{HRD}/HRD (io), C16 D58 / HDDS (io), C17 D61 / Reserved (io), C18 DBB / ~{IRQ3} (io), C19 Reserved / BADDR29 / ~{IRQ2} (io), D4 ~{IRQ2} / DP2 / ~{EXT_DBG2} (io), D5 ~{IRQ6} / DP6 / ~{DACK3} (io), D6 D8 (io), D7 D14 (io), D8 D19 (io), D9 D24 (io), D10 D29 (io), D11 D34 / HD2 (io), D12 D39 / HD7 (io), D13 D43 / HD11 (io), D14 D48 / HA0 (io), D15 D52 / ~{HCS1} (io), D16 D57 / HDSP (io), D17 PWE5 / PSDDQM5 / PBS5 (io), D18 ~{IRQ1} / ~{GBL} (io), D19 BADDR27 (io), E7 D13 (io), E14 D47 / HD15 (io), E16 D56 / ~{HACK}/HACK / ~{HRRQ}/HRRQ (io), E17 ~{PSDA10} / PGPL0 (io), E19 ~{PSDCAS} / PGPL3 (io), F6 ~{IRQ7} / DP7 / ~{DACK4} (io), F8 D18 (io), F10 D28 (io), F12 D38 / HD6 (io), F14 PSDWE / PGPL1 (io), F17 ~{PWE7} / PSDDQM7 / PBS7 (io), F19 ~{BCTL0} (io), G7 D12 (io), G9 D23 (io), G11 D33 / HD1 (io), G13 ~{PSDVAL} (io), G17 ~{TEA} (io), G19 ~{POE} / PSDRAS / PGPL2 (io), H13 Reserved / BADDR31 / ~{IRQ5} (io), H14 Reserved / BADDR30 / ~{IRQ3} (io), H17 ~{BR} (io), H18 ALE (io), H19 ~{PWE4} / PSDDQM4 / PBS4 (io), J13 ~{TA} (io), J17 ~{PSDAMUX} / PGPL5 (io), J18 ~{PGTA} / PUPMWAIT / PPBS / PGPL4 (io), J19 ~{PWE3} / PSDDQM3 / PBS3 (io), K14 ~{PWE2} / PSDDQM2 / PBS2 (io), K17 ~{PWE1} / PSDDQM1 / PBS1 (io), K18 ~{PWE0} / PSDDQM0 / PBS0 (io), K19 ~{CS2} (io), L13 ~{CS6} (io), L17 ~{CS1} (io), L18 ~{CS3} (io), L19 ~{BCTL1} (io), M13 A21 (io), M14 A26 (io), M16 ~{CS0} (io), M17 ~{CS5} (io), M18 ~{CS7} (io), M19 ~{CS4} (io), N11 TSIZ3 (io), N12 TT1 (io), N13 TT0 (io), N14 A1 (io), N17 A28 (io), N18 A30 (io), N19 A31 (io), P17 A23 (io), P18 A27 (io), P19 A29 (io), R16 A15 (io), R17 A19 (io), R18 A24 (io), R19 A25 (io), T12 ~{AACK} (io), T13 ~{TS} (io), T14 A3 (io), T16 A12 (io), T17 A16 (io), T18 A20 (io), T19 A22 (io), U5 ~{NMI} (in), U12 ~{ARTRY} (in), U13 ~{TBST} (io), U14 TT2 (io), U15 A4 (io), U16 A8 (io), U17 A11 (io), U18 A17 (io), U19 A18 (io), V5 ~{NMI_OUT} (out), V11 ABB / ~{IRQ2} (io), V12 ~{BG} (io), V13 TSIZ0 (io), V14 TT3 (io), V15 A2 (io), V16 A6 (io), V17 A9 (io), V18 A13 (io), V19 A14 (io), W11 ~{IRQ7} / ~{INT_OUT} (io), W12 TSIZ2 (io), W13 TSIZ1 (io), W14 TT4 (io), W15 A0 (io), W16 A5 (io), W17 A7 (io), W18 A10 (io)
part C pins: E4 VDDH (power), E5 VDD (power), E6 VDDH (power), E8 VDDH (power), E9 VDD (power), E10 VDDH (power), E11 VDDH (power), E12 VDD (power), E13 VDDH (power), E15 VDDH (power), F4 VDD (power), F5 GND (power), F7 GND (power), F9 GND (power), F11 GND (power), F13 GND (power), F15 GND (power), F16 VDD (power), G5 VDDH (power), G6 GND (power), G8 GND (power), G10 GND (power), G12 GND (power), G14 GND (power), G15 VDDH (power), G16 VDDH (power), H5 GND (power), H7 GND (power), H15 GND (power), H16 VDD (power), J4 VDD (power), J5 GND (power), J6 GND (power), J14 GND (power), J15 VDDH (power), J16 VDDH (power), K5 VDDH (power), K6 GND (power), K7 GND (power), K13 GND (power), K15 GND (power), K16 VDDH (power), L4 VDD (power), L5 GND (power), L6 GND (power), L14 GND (power), L15 GND (power), L16 VDD (power), M4 VDDH (power), M5 GND (power), M15 GND (power), N4 VDD (power), N6 GND (power), N9 GND (power), N15 VDDH (power), N16 VDDH (power), P6 GND (power), P7 GND (power), P9 GND (power), P11 GND (power), P12 GND (power), P13 GND (power), P14 GND (power), P15 GND (power), P16 VDD (power), R6 VDDH (power), R7 VDDH (power), R8 VDD (power), R9 VDDH (power), R10 VDDH (power), R11 VDD (power), R12 VDDH (power), R13 VDD (power), R14 VDDH (power), R15 VDDH (power), T7 VCCSYN1 (power), T15 VDDH (power), U7 GNDSYN1 (power), V7 GNDSYN (power), W7 VCCSYN (power)

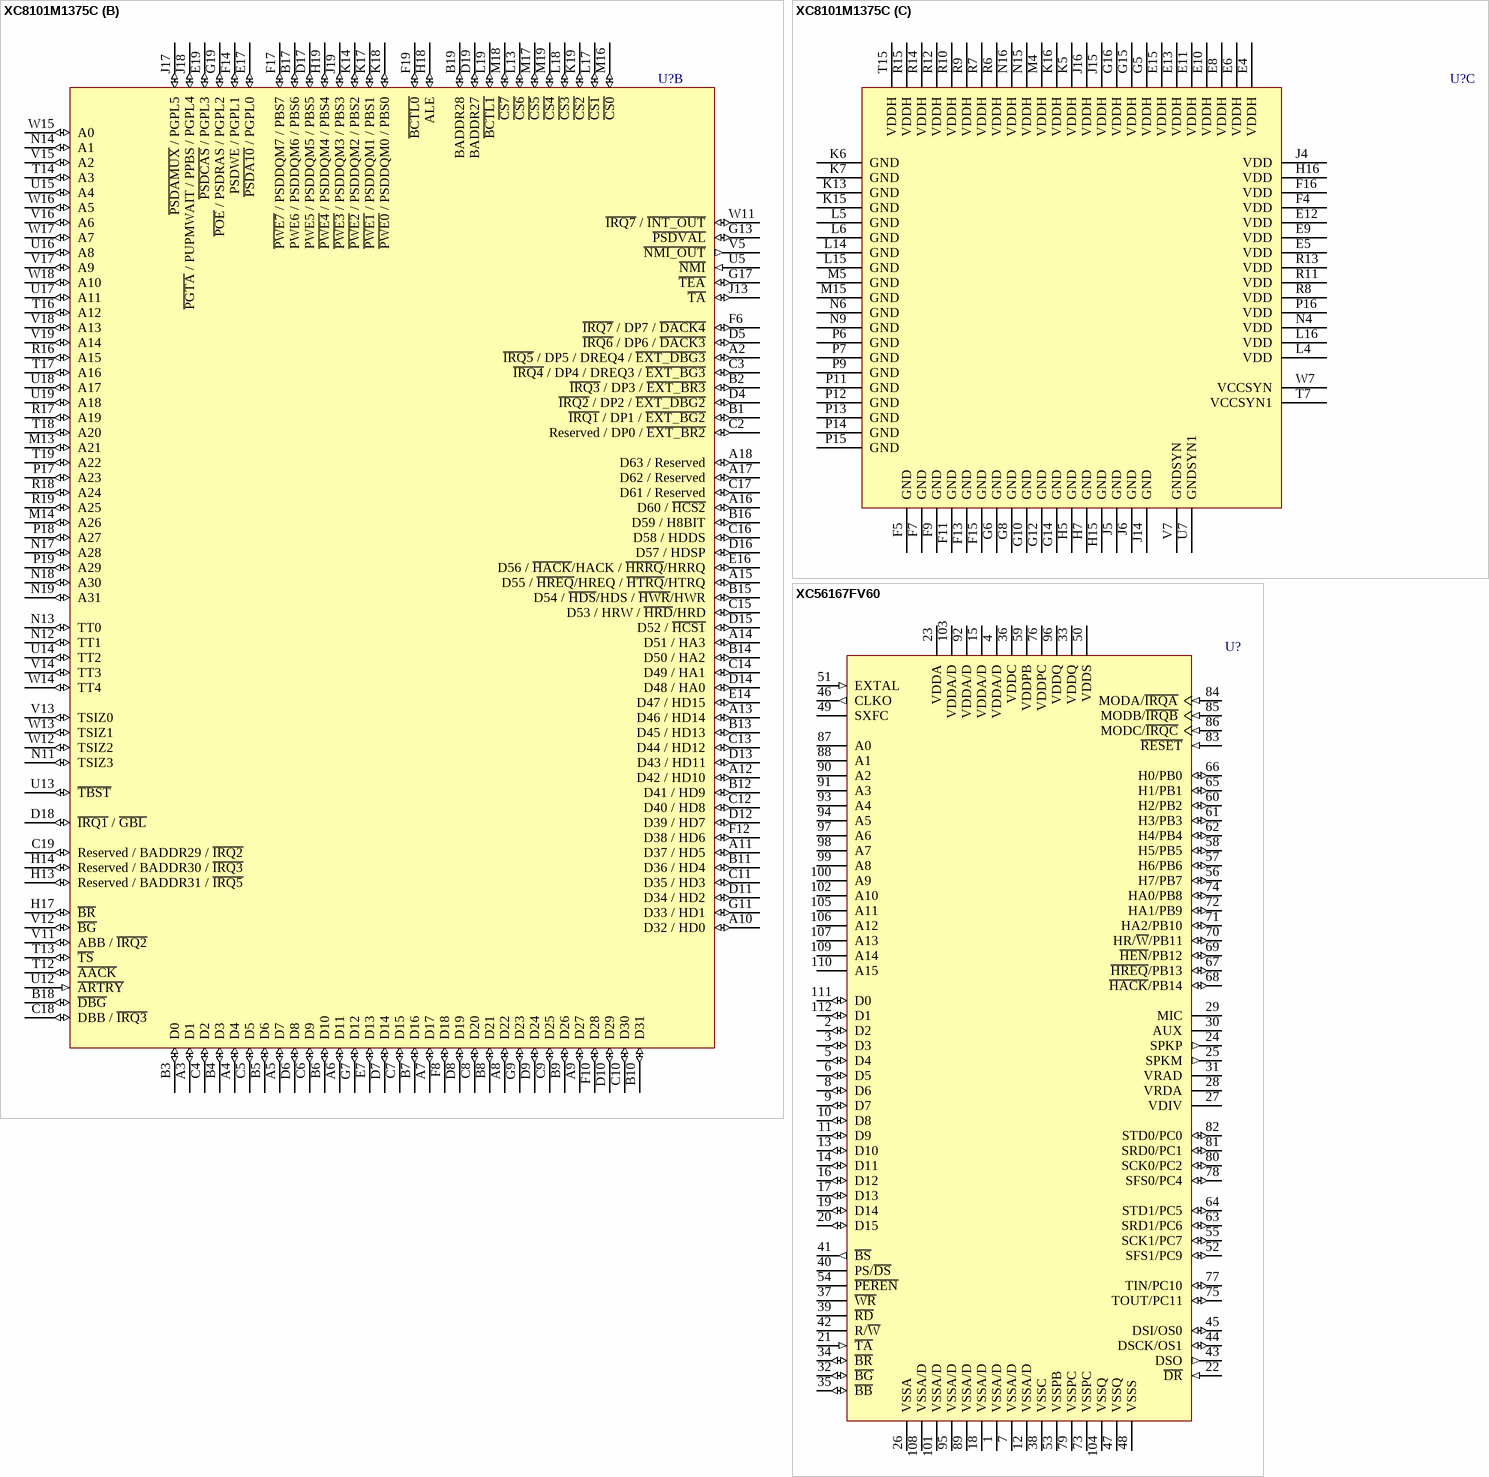
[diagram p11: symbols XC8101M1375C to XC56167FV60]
